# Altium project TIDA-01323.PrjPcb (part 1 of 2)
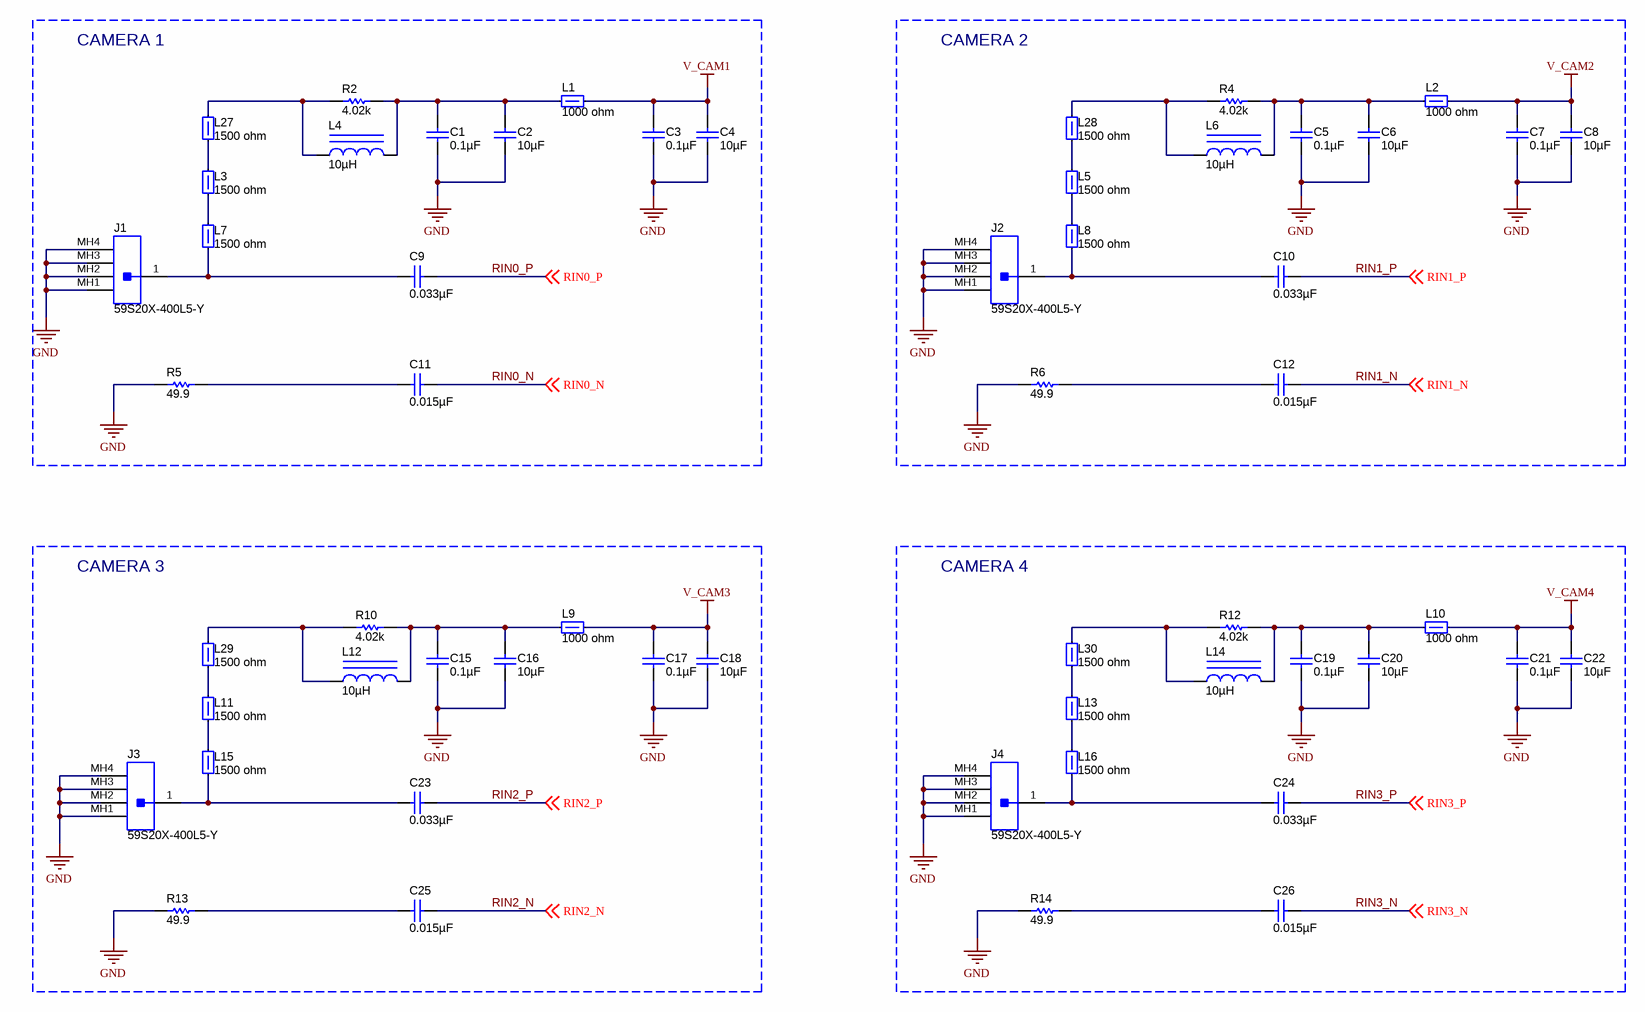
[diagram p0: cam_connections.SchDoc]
CopyrightYear: 2017; EVM_Orderable: NO; PCB_Layout: Krypton Solutions; PCB_Rev: E1.0; PRJ_Customer: Public Release; PRJ_Engineer: Jeramie Bianchi; PRJ_Number: TIDA-01323; PRJ_Title: Four Channel Camera Board for TDA2Plus; SCH_Rev: E1.0; TechSupport: http://www.ti.com/support; TID: 01323
8 sheets, 311 parts. Net scope: global (net labels, ports and power ports of the same name join across sheets).
Board file: TIDA-01323.PcbDoc
Sheets:
  cam_connections.SchDoc
  V_Batt_Supply.SchDoc
  Bucks.SchDoc
  Deserializer.SchDoc
  Connectors.SchDoc
  Camera_Power.SchDoc
  uC.SchDoc
  Hardware.SchDoc

## Sheet cam_connections.SchDoc: cam_connections
size 431 x 279 mm; Date: Not shown in title block; ApprovedBy: Not shown in title block; CheckedBy: Not shown in title block; Author: Not shown in title block; CompanyName: Not shown in title block; DrawnBy: Jeramie Bianchi; Engineer: Not shown in title block; Organization: Not shown in title block; Address1: Not shown in title block; Address2: Not shown in title block; Address3: Not shown in title block; Address4: Not shown in title block; DocumentNumber: 1; Revision: Use project parameter SCH_Rev; SheetNumber: 1; SheetTotal: 8; PageSetup: Record=PageOptions¦CenterHorizontal=True¦CenterVertical=True¦PrintScale=0.64¦XCorrection=1.00¦YCorrection=1.00¦PrintKind=0¦BorderSize=5000000¦LeftOffset=0¦BottomOffset=0¦Orientation=2¦PaperLength=1000¦PaperWidth=1000¦Scale=100¦PaperSource=15¦PrintQuality=-3¦MediaType=1¦DitherType=10¦PrintScaleMode=1¦PaperKind=11x17¦PaperIndex=17

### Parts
C1  ValueDisplayed: 0.1µF  [0402]  (hidden comment: C1005X7R1H104K050BB)
C2  ValueDisplayed: 10µF  [0603L]  (hidden comment: C1608X5R1E106M080AC)
C3  ValueDisplayed: 0.1µF  [0402]  (hidden comment: C1005X7R1H104K050BB)
C4  ValueDisplayed: 10µF  [0603L]  (hidden comment: C1608X5R1E106M080AC)
C5  ValueDisplayed: 0.1µF  [0402]  (hidden comment: C1005X7R1H104K050BB)
C6  ValueDisplayed: 10µF  [0603L]  (hidden comment: C1608X5R1E106M080AC)
C7  ValueDisplayed: 0.1µF  [0402]  (hidden comment: C1005X7R1H104K050BB)
C8  ValueDisplayed: 10µF  [0603L]  (hidden comment: C1608X5R1E106M080AC)
C9  ValueDisplayed: 0.033µF  [0402]  (hidden comment: CGA2B3X7R1H333K050BB)
C10  ValueDisplayed: 0.033µF  [0402]  (hidden comment: CGA2B3X7R1H333K050BB)
C11  ValueDisplayed: 0.015µF  [0402]  (hidden comment: CGA2B3X7R1H153K050BB)
C12  ValueDisplayed: 0.015µF  [0402]  (hidden comment: CGA2B3X7R1H153K050BB)
C15  ValueDisplayed: 0.1µF  [0402]  (hidden comment: C1005X7R1H104K050BB)
C16  ValueDisplayed: 10µF  [0603L]  (hidden comment: C1608X5R1E106M080AC)
C17  ValueDisplayed: 0.1µF  [0402]  (hidden comment: C1005X7R1H104K050BB)
C18  ValueDisplayed: 10µF  [0603L]  (hidden comment: C1608X5R1E106M080AC)
C19  ValueDisplayed: 0.1µF  [0402]  (hidden comment: C1005X7R1H104K050BB)
C20  ValueDisplayed: 10µF  [0603L]  (hidden comment: C1608X5R1E106M080AC)
C21  ValueDisplayed: 0.1µF  [0402]  (hidden comment: C1005X7R1H104K050BB)
C22  ValueDisplayed: 10µF  [0603L]  (hidden comment: C1608X5R1E106M080AC)
C23  ValueDisplayed: 0.033µF  [0402]  (hidden comment: CGA2B3X7R1H333K050BB)
C24  ValueDisplayed: 0.033µF  [0402]  (hidden comment: CGA2B3X7R1H333K050BB)
C25  ValueDisplayed: 0.015µF  [0402]  (hidden comment: CGA2B3X7R1H153K050BB)
C26  ValueDisplayed: 0.015µF  [0402]  (hidden comment: CGA2B3X7R1H153K050BB)
J1  59S20X-400L5-Y  [Rosenberger_59S20X-400L5]
J2  59S20X-400L5-Y  [Rosenberger_59S20X-400L5]
J3  59S20X-400L5-Y  [Rosenberger_59S20X-400L5]
J4  59S20X-400L5-Y  [Rosenberger_59S20X-400L5]
L1  value 1000 ohm  [0603L]  (hidden comment: BLM18AG102SN1D)
L2  value 1000 ohm  [0603L]  (hidden comment: BLM18AG102SN1D)
L3  value 1500 ohm  [0603]  (hidden comment: BLM18HE152SN1D)
L4  ValueDisplayed: 10µH  [LQH3NP_G0]  (hidden comment: LQH3NPN100NG0)
L5  value 1500 ohm  [0603]  (hidden comment: BLM18HE152SN1D)
L6  ValueDisplayed: 10µH  [LQH3NP_G0]  (hidden comment: LQH3NPN100NG0)
L7  value 1500 ohm  [0603]  (hidden comment: BLM18HE152SN1D)
L8  value 1500 ohm  [0603]  (hidden comment: BLM18HE152SN1D)
L9  value 1000 ohm  [0603L]  (hidden comment: BLM18AG102SN1D)
L10  value 1000 ohm  [0603L]  (hidden comment: BLM18AG102SN1D)
L11  value 1500 ohm  [0603]  (hidden comment: BLM18HE152SN1D)
L12  ValueDisplayed: 10µH  [LQH3NP_G0]  (hidden comment: LQH3NPN100NG0)
L13  value 1500 ohm  [0603]  (hidden comment: BLM18HE152SN1D)
L14  ValueDisplayed: 10µH  [LQH3NP_G0]  (hidden comment: LQH3NPN100NG0)
L15  value 1500 ohm  [0603]  (hidden comment: BLM18HE152SN1D)
L16  value 1500 ohm  [0603]  (hidden comment: BLM18HE152SN1D)
L27  value 1500 ohm  [0603]  (hidden comment: BLM18HE152SN1D)
L28  value 1500 ohm  [0603]  (hidden comment: BLM18HE152SN1D)
L29  value 1500 ohm  [0603]  (hidden comment: BLM18HE152SN1D)
L30  value 1500 ohm  [0603]  (hidden comment: BLM18HE152SN1D)
R2  ValueDisplayed: 4.02k  [0603]  (hidden comment: CRCW06034K02FKEA)
R4  ValueDisplayed: 4.02k  [0603]  (hidden comment: CRCW06034K02FKEA)
R5  ValueDisplayed: 49.9  [0402]  (hidden comment: CRCW040249R9FKED)
R6  ValueDisplayed: 49.9  [0402]  (hidden comment: CRCW040249R9FKED)
R10  ValueDisplayed: 4.02k  [0603]  (hidden comment: CRCW06034K02FKEA)
R12  ValueDisplayed: 4.02k  [0603]  (hidden comment: CRCW06034K02FKEA)
R13  ValueDisplayed: 49.9  [0402]  (hidden comment: CRCW040249R9FKED)
R14  ValueDisplayed: 49.9  [0402]  (hidden comment: CRCW040249R9FKED)

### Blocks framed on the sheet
CAMERA 1: C1-C4 C9 C11 J1 L1 L3 L4 L7 L27 R2 R5
CAMERA 2: C5-C8 C10 C12 J2 L2 L5 L6 L8 L28 R4 R6
CAMERA 3: C15-C18 C23 C25 J3 L9 L11 L12 L15 L29 R10 R13
CAMERA 4: C19-C22 C24 C26 J4 L10 L13 L14 L16 L30 R12 R14

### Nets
GND: C1.2 C2.2 C3.2 C4.2 C5.2 C6.2 C7.2 C8.2 C15.2 C16.2 C17.2 C18.2 C19.2 C20.2 C21.2 C22.2 J1.MH1 J1.MH2 J1.MH3 J1.MH4 J2.MH1 J2.MH2 J2.MH3 J2.MH4 J3.MH1 J3.MH2 J3.MH3 J3.MH4 J4.MH1 J4.MH2 J4.MH3 J4.MH4 R5.1 R6.1 R13.1 R14.1
V_CAM1: C3.1 C4.1 L1.1
V_CAM2: C7.1 C8.1 L2.1
V_CAM3: C17.1 C18.1 L9.1
V_CAM4: C21.1 C22.1 L10.1
RIN0_N: C11.2 ; off-sheet RIN0_N
RIN0_P: C9.2 ; off-sheet RIN0_P
RIN1_N: C12.2 ; off-sheet RIN1_N
RIN1_P: C10.2 ; off-sheet RIN1_P
RIN2_N: C25.2 ; off-sheet RIN2_N
RIN2_P: C23.2 ; off-sheet RIN2_P
RIN3_N: C26.2 ; off-sheet RIN3_N
RIN3_P: C24.2 ; off-sheet RIN3_P
NetC1_1: C1.1 C2.1 L1.2 L4.2 R2.2
NetC5_1: C5.1 C6.1 L2.2 L6.2 R4.2
NetC9_1: C9.1 J1.1 L7.1
NetC10_1: C10.1 J2.1 L8.1
NetC11_1: C11.1 R5.2
NetC12_1: C12.1 R6.2
NetC15_1: C15.1 C16.1 L9.2 L12.2 R10.2
NetC19_1: C19.1 C20.1 L10.2 L14.2 R12.2
NetC23_1: C23.1 J3.1 L15.1
NetC24_1: C24.1 J4.1 L16.1
NetC25_1: C25.1 R13.2
NetC26_1: C26.1 R14.2
NetL3_1: L3.1 L7.2
NetL3_2: L3.2 L27.1
NetL4_1: L4.1 L27.2 R2.1
NetL5_1: L5.1 L8.2
NetL5_2: L5.2 L28.1
NetL6_1: L6.1 L28.2 R4.1
NetL11_1: L11.1 L15.2
NetL11_2: L11.2 L29.1
NetL12_1: L12.1 L29.2 R10.1
NetL13_1: L13.1 L16.2
NetL13_2: L13.2 L30.1
NetL14_1: L14.1 L30.2 R12.1

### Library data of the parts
C1 C3 C5 C7 C15 C17 C19 C21 = C1005X7R1H104K050BB: CAP, CERM, 0.1 µF, 50 V, +/- 10%, X7R, 0402; Manufacturer: TDK; Polarized: N; CompType: Capacitor; Value: 0.1uF; U/M: EA; Cap_F: 0.0000001; Tolerance_%: 10; Value1: Unknown; VDC_V: 50; Value2: 50V; TaMin_C: -55; TaMax_C: 125
C2 C4 C6 C8 C16 C18 C20 C22 = C1608X5R1E106M080AC: CAP, CERM, 10 µF, 25 V, +/- 20%, X5R, 0603; Manufacturer: TDK; Polarized: N; CompType: Capacitor; Value: 10uF; U/M: EA; Cap_F: 0.00001; Tolerance_%: 20; ESR_ohm: 0.004639; Value1: 0.004639 ohm; VDC_V: 25; Value2: 25V; IRMS_A: 2.41407; TaMin_C: -55; TaMax_C: 85; Cap_Case: 0603; SizeArea_mm2: 1.28; SizeAreaWB_mm2: 4.68; SizeX_mm: 1.6; SizeY_mm: 0.8; SizeZ_mm: 1; AEC Category: Q200
C9 C10 C23 C24 = CGA2B3X7R1H333K050BB: CAP, CERM, 0.033 µF, 50 V, +/- 10%, X7R, AEC-Q200 Grade 1, 0402; Manufacturer: TDK; Polarized: N; CompType: Capacitor; Value: 0.033uF; U/M: EA; Cap_F: 0.000000033; Tolerance_%: 10; ESR_ohm: 0.098477; Value1: 0.098477 ohm; VDC_V: 50; Value2: 50V; IRMS_A: 0.53078; TaMin_C: -55; TaMax_C: 125; SizeArea_mm2: 0.5; SizeAreaWB_mm2: 3; SizeX_mm: 1; SizeZ_mm: 0.6; AEC Category: Q200; AEC Qualified: Y
C11 C12 C25 C26 = CGA2B3X7R1H153K050BB: CAP, CERM, 0.015 µF, 50 V,+/- 10%, X7R, AEC-Q200 Grade 1, 0402; Manufacturer: TDK; Polarized: N; CompType: Capacitor; Value: 0.015uF; U/M: EA; Cap_F: 0.000000015; Tolerance_%: 10; ESR_ohm: 0.2162; Value1: 0.2162 ohm; VDC_V: 50; Value2: 50V; IRMS_A: 0.379389; TaMin_C: -55; TaMax_C: 125; SizeArea_mm2: 0.5; SizeAreaWB_mm2: 3; SizeX_mm: 1; SizeZ_mm: 0.6; AEC Category: Q200; AEC Qualified: Y
J1-J4 = 59S20X-400L5-Y: RIGHT ANGLE PLUG FOR PCB; Manufacturer: Rosenberger; SymbolCreator: x0208325
L1 L2 L9 L10 = BLM18AG102SN1D: Ferrite Bead, 1000 ohm @ 100 MHz, 0.4 A, 0603; Manufacturer: MuRata; Imax_A: 0.4; DCR_ohm: 0.5; Value1: 0.5 ohm; Value2: 0.4A; ZTyp@100MHz_Ohm: 1000
L3 L5 L11 L13 L28-L30 = BLM18HE152SN1D: Ferrite Bead, 1500 ohm @ 100 MHz, 0.5 A, 0603; Manufacturer: MuRata; Imax_A: 0.5; Value1: 0.5 ohm; Value2: 0.5A; SizeAreaWB_mm2: 4.68; SizeArea_mm2: 1.28; SizeX_mm: 1.6; SizeY_mm: 0.8; SizeZ_mm: 1; ZTyp@100MHz_Ohm: 1500
L4 L6 L12 L14 = LQH3NPN100NG0: Inductor, Wirewound, Ferrite, 10 µH, 0.5 A, 0.57 ohm, SMD; Manufacturer: MuRata; Value: 10uH; Ind_H: 10.0E-6; Imax_A: 0.5; Irms: 0.63A @ 40C rise; Isat: 0.5A @ 30% inductance drop; DCR_ohm: 0.57; Value2: 0.5A; SizeAreaWB_mm2: 16; SizeArea_mm2: 9; SizeX_mm: 3; SizeZ_mm: 1; AEC Category: Q200
L7 L8 L15 L16 = BLM18HE152SN1D: Ferrite Bead, 1500 ohm @ 100 MHz, 0.5 A, 0603; Manufacturer: MuRata; Imax_A: 0.5; Value1: 0.5 ohm; Value2: 0.5A; ZTyp@100MHz_Ohm: 1500
L27 = BLM18HE152SN1D: Ferrite Bead, 1500 ohm @ 100 MHz, 0.5 A, 0603; Manufacturer: MuRata; Value1: 0.5 ohm; Value2: 0.5A; Imax_A: 0.5; SizeAreaWB_mm2: 4.68; SizeArea_mm2: 1.28; SizeX_mm: 1.6; SizeY_mm: 0.8; SizeZ_mm: 1; ZTyp@100MHz_Ohm: 1500
R2 R4 R10 R12 = CRCW06034K02FKEA: RES, 4.02 k, 1%, 0.1 W, 0603; Manufacturer: Vishay-Dale; CompType: Resistor; Value: 4.02k; Res_ohm: 4020; Value_Code: 4k02; Tolerance_%: 1; Power_W: 0.1; Value2: 0.1W; VDC_V: 75; TempCo: 100 ppm/C; EIA_Code: E96; U/M: EA; SizeArea_mm2: 1.28; SizeX_mm: 1.6; SizeY_mm: 0.8; AEC Category: Q200
R5 R6 R13 R14 = CRCW040249R9FKED: RES, 49.9, 1%, 0.063 W, 0402; Manufacturer: Vishay-Dale; CompType: Resistor; Value: 49.9; Value_Code: 49R9; Tolerance_%: 1; Power_W: 0.063; Value2: 0.063W; VDC_V: 50; TempCo: 100 ppm/C; EIA_Code: E96; U/M: EA; SizeArea_mm2: 0.5; SizeZ_mm: 0.6; AEC Category: Q200

## Sheet V_Batt_Supply.SchDoc: V_Batt_Supply
size 431 x 279 mm; Date: Not shown in title block; ApprovedBy: Not shown in title block; CheckedBy: Not shown in title block; Author: Not shown in title block; CompanyName: Not shown in title block; DrawnBy: Jeramie Bianchi; Engineer: Not shown in title block; Organization: Not shown in title block; Address1: Not shown in title block; Address2: Not shown in title block; Address3: Not shown in title block; Address4: Not shown in title block; DocumentNumber: 2; Revision: Use project parameter SCH_Rev; SheetNumber: 2; SheetTotal: 8; PageSetup: Record=PageOptions¦CenterHorizontal=True¦CenterVertical=True¦PrintScale=0.62¦XCorrection=1.00¦YCorrection=1.00¦PrintKind=0¦BorderSize=5000000¦LeftOffset=0¦BottomOffset=0¦Orientation=2¦PaperLength=1000¦PaperWidth=1000¦Scale=100¦PaperSource=15¦PrintQuality=600¦MediaType=1¦DitherType=10¦PrintScaleMode=1¦PaperKind=Letter
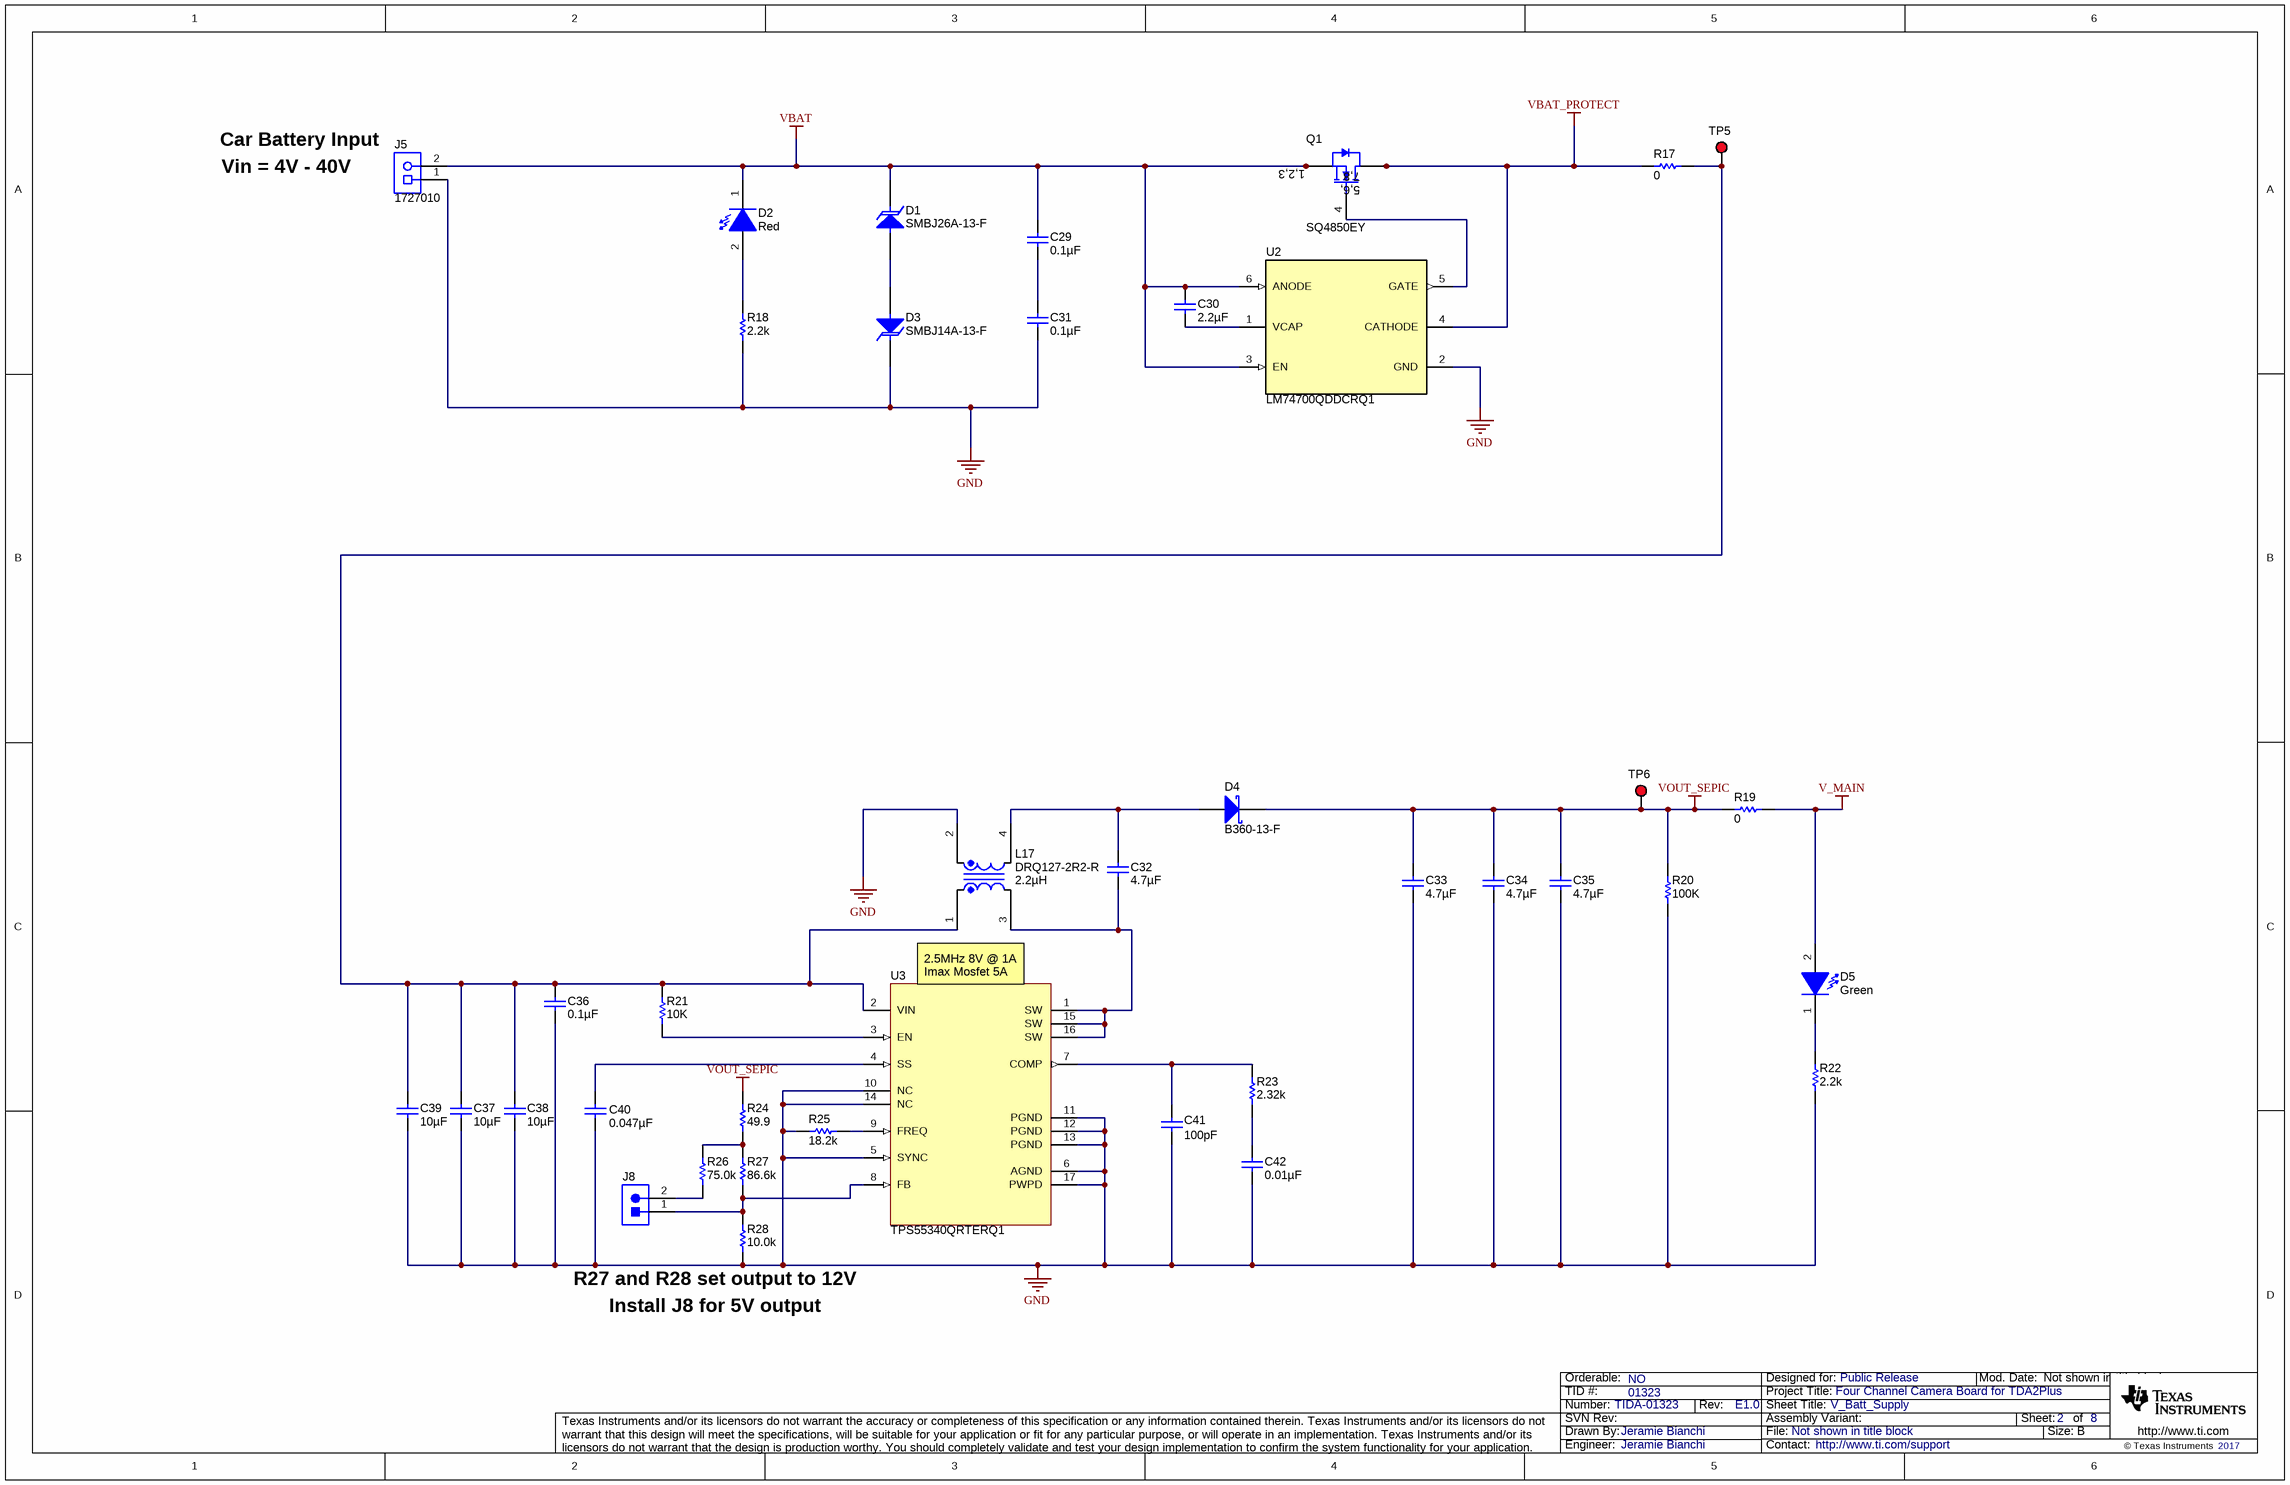
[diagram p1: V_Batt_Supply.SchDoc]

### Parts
C29  ValueDisplayed: 0.1µF  [0402]  (hidden comment: CGA2B3X7R1H104M050BB)
C30  ValueDisplayed: 2.2µF  [0603]  (hidden comment: GRM188R71A225KE15D)
C31  ValueDisplayed: 0.1µF  [0402]  (hidden comment: CGA2B3X7R1H104M050BB)
C32  ValueDisplayed: 4.7µF  [1206_190]  (hidden comment: C3216X7R1E475M160AC)
C33  ValueDisplayed: 4.7µF  [1206_190]  (hidden comment: C3216X7R1E475M160AC)
C34  ValueDisplayed: 4.7µF  [1206_190]  (hidden comment: C3216X7R1E475M160AC)
C35  ValueDisplayed: 4.7µF  [1206_190]  (hidden comment: C3216X7R1E475M160AC)
C36  ValueDisplayed: 0.1µF  [0402]  (hidden comment: GRM155R70J104KA01D)
C37  ValueDisplayed: 10µF  [1206_180]  (hidden comment: GRM31CR71E106KA12L)
C38  ValueDisplayed: 10µF  [1206_180]  (hidden comment: GRM31CR71E106KA12L)
C39  ValueDisplayed: 10µF  [1206_180]  (hidden comment: GRM31CR71E106KA12L)
C40  ValueDisplayed: 0.047µF  [0402]  (hidden comment: GRM155R70J473KA01D)
C41  ValueDisplayed: 100pF  [0402]  (hidden comment: CC0402KRX7R9BB101)
C42  ValueDisplayed: 0.01µF  [0402]  (hidden comment: GRM155R71C103KA01D)
D1  SMBJ26A-13-F  [SMB]
D2  value Red  [SML-P1_RED]  (hidden comment: SML-P12UTT86)
D3  SMBJ14A-13-F  [SMB]
D4  B360-13-F  [SMC]
D5  value Green  [SML-P1_GREEN]  (hidden comment: SML-P12PTT86)
J5  1727010  [PhoenixConact_1727010]
J8  PEC02SAAN  [CONN_PEC02SAAN]  (value not drawn)
L17  DRQ127-2R2-R  ValueDisplayed: 2.2µH  [DRQ127]
Q1  SQ4850EY  [SOIC-8]
R17  ValueDisplayed: 0  [2010]  (hidden comment: CRCW20100000Z0EF)
R18  ValueDisplayed: 2.2k  [0402]  (hidden comment: CRCW04022K20JNED)
R19  value 0  [0805_HV]  (hidden comment: CRCW08050000Z0EA)
R20  value 100K  [1206]  (hidden comment: CRCW1206100KJNEA)
R21  value 10K  [0402]  (hidden comment: CRCW040210K0JNED)
R22  ValueDisplayed: 2.2k  [0402]  (hidden comment: CRCW04022K20JNED)
R23  value 2.32k  [0402]  (hidden comment: CRCW04022K32FKED)
R24  value 49.9  [0402]  (hidden comment: CRCW040249R9FKED)
R25  value 18.2k  [0402]  (hidden comment: CRCW040218K2FKED)
R26  ValueDisplayed: 75.0k  [0402]  (hidden comment: CRCW040275K0FKED)
R27  ValueDisplayed: 86.6k  [0402]  (hidden comment: CRCW040286K6FKED)
R28  ValueDisplayed: 10.0k  [0402]  (hidden comment: CRCW040210K0FKED)
TP5  5000  [Keystone5000]  (value not drawn)
TP6  5000  [Keystone5000]  (value not drawn)
U2  LM74700QDDCRQ1  [DDC0006A_N]
U3  TPS55340QRTERQ1  [RTE0016C]

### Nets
GND: C31.2 C33.2 C34.2 C35.2 C36.2 C37.2 C38.2 C39.2 C40.2 C41.2 C42.2 D3.1(K) J5.1 L17.2 R18.1 R20.1 R22.1 R25.1 R28.1 U2.2(GND) U3.5(SYNC) U3.6(AGND) U3.10(NC) U3.11(PGND) U3.12(PGND) U3.13(PGND) U3.14(NC) U3.17(PWPD)
V_MAIN: D5.2(A) R19.2
VBAT: C29.1 C30.1 D1.1(K) D2.1(K) J5.2 Q1.1(S) Q1.2(S) Q1.3(S) U2.3(EN) U2.6(ANODE)
VBAT_PROTECT: Q1.5(D) Q1.6(D) Q1.7(D) Q1.8(D) R17.1 U2.4(CATHODE)
VOUT_SEPIC: C33.1 C34.1 C35.1 D4.1(K) R19.1 R20.2 R24.1 TP6.1
NetC29_2: C29.2 C31.1
NetC30_2: C30.2 U2.1(VCAP)
NetC32_1: C32.1 D4.2(A) L17.4
NetC32_2: C32.2 L17.3 U3.1(SW) U3.15(SW) U3.16(SW)
NetC36_1: C36.1 C37.1 C38.1 C39.1 L17.1 R17.2 R21.1 TP5.1 U3.2(VIN)
NetC40_1: C40.1 U3.4(SS)
NetC41_1: C41.1 R23.2 U3.7(COMP)
NetC42_1: C42.1 R23.1
NetD1_2: D1.2(A) D3.2(A)
NetD2_2: D2.2(A) R18.2
NetD5_1: D5.1(K) R22.2
NetJ8_1: J8.1 R27.1 R28.2 U3.8(FB)
NetJ8_2: J8.2 R26.1
NetQ1_4: Q1.4(G) U2.5(GATE)
NetR21_2: R21.2 U3.3(EN)
NetR24_2: R24.2 R26.2 R27.2
NetR25_2: R25.2 U3.9(FREQ)

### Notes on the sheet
- Vin = 4V - 40V
- (near J5) Car Battery Input
- 2.5MHz 8V @ 1A
  Imax Mosfet 5A
- (near R28) R27 and R28 set output to 12V
- (near R28) Install J8 for 5V output

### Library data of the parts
C29 C31 = CGA2B3X7R1H104M050BB: CAP, CERM, 0.1 µF, 50 V, +/- 20%, X7R, AEC-Q200 Grade 1, 0402; Manufacturer: TDK; Polarized: N; CompType: Capacitor; Value: 0.1uF; U/M: EA; Cap_F: 0.0000001; Tolerance_%: 20; Value1: Unknown; VDC_V: 50; Value2: 50V; TaMin_C: -55; TaMax_C: 125; AEC Category: Q200; AEC Qualified: Y; AEC Grade: 1
C30 = GRM188R71A225KE15D: CAP, CERM, 2.2 µF, 10 V, +/- 10%, X7R, 0603; Manufacturer: MuRata; Polarized: N; CompType: Capacitor; Value: 2.2uF; U/M: EA; Cap_F: 0.0000022; Tolerance_%: 10; ESR_ohm: 0.009; Value1: 0.009 ohm; Value2: 10V; TaMin_C: -55; TaMax_C: 125
C32-C35 = C3216X7R1E475M160AC: CAP, CERM, 4.7 µF, 25 V, +/- 20%, X7R, 1206_190; Manufacturer: TDK; Polarized: N; CompType: Capacitor; Value: 4.7uF; U/M: EA; Cap_F: 0.0000047; Tolerance_%: 20; Value1: Unknown; VDC_V: 25; Value2: 25V; TaMin_C: -55; TaMax_C: 125; Cap_Case: 1206; SizeArea_mm2: 5.12; SizeAreaWB_mm2: 10.92; SizeX_mm: 3.2; SizeY_mm: 1.6; SizeZ_mm: 1.9; AEC Category: Q200
C36 = GRM155R70J104KA01D: Cap, Cer-X7R, 0.1uF, 6.3V, 10%, 0402; Manufacturer: MuRata; Polarized: N; CompType: Capacitor; U/M: EA; Cap_F: 0.0000001; Tolerance_%: 10; Value1: Unknown; VDC_V: 6.3; TempCo: X7R; TaMin_C: -55; TaMax_C: 125; EN: 102-1-01892; Mfg: MURATA MANUFACTURING CO,LTD; Onhand: 0
C37-C39 = GRM31CR71E106KA12L: CAP, CERM, 10 µF, 25 V, +/- 10%, X7R, 1206; Manufacturer: MuRata; Polarized: N; CompType: Capacitor; Value: 10uF; U/M: EA; Cap_F: 0.00001; Tolerance_%: 10; Value1: Unknown; VDC_V: 25; Value2: 25V; TaMin_C: -55; TaMax_C: 125; Cap_Case: 2220; SizeArea_mm2: 5.12; SizeAreaWB_mm2: 10.92; SizeX_mm: 3.2; SizeY_mm: 1.6; SizeZ_mm: 1.8; AEC Category: Q200
C40 = GRM155R70J473KA01D: Cap, Cer-X7R, 0.047uF, 6.3V, 10%, 0402; Manufacturer: MuRata; Polarized: N; CompType: Capacitor; U/M: EA; Cap_F: 0.000000047; Tolerance_%: 10; Value1: Unknown; VDC_V: 6.3; TempCo: X7R; TaMin_C: -55; TaMax_C: 125; EN: 102-1-01894; Mfg: MURATA MANUFACTURING CO,LTD; Onhand: 0
C41 = CC0402KRX7R9BB101: Cap, Cer-X7R, 100pF, 50V, 10%, 0402; Manufacturer: Yageo America; PART Name: SCH_LIB\CAP_NP; Polarized: N; CompType: Capacitor; U/M: EA; Cap_F: 0.0000000001; Tolerance_%: 10; Value1: Unknown; VDC_V: 50; TempCo: X7R; TaMin_C: -55; TaMax_C: 125; DECAL Name: 0402,0402_HD; EN: 102-1-00053; Mfg: YAGEO; Onhand: 16933
C42 = GRM155R71C103KA01D: Cap, Cer-X7R, 10000pF, 16V, 10%, 0402; Manufacturer: MuRata; Polarized: N; CompType: Capacitor; U/M: EA; Cap_F: 0.00000001; Tolerance_%: 10; Value1: Unknown; VDC_V: 16; TempCo: X7R; TaMin_C: -55; TaMax_C: 125; EN: 102-1-01895; Mfg: MURATA MANUFACTURING CO,LTD; Onhand: 0
D1 = SMBJ26A-13-F: Diode, TVS, Uni, 26 V, 600 W, SMB; Manufacturer: Diodes Inc.; Value: 26V; U/M: EA; Power_W: 5; Vr_V: 26; Value1: 5W
D2 = SML-P12UTT86: LED, Red, SMD; Manufacturer: Rohm; Type: AlInGaP; Vf_V: 2; Value2: 2V; Io_A: 0.02; Value1: W; U/M: EA
D3 = SMBJ14A-13-F: Diode, TVS, Uni, 14 V, 600 W, SMB; Manufacturer: Diodes Inc.; Value: 14V; U/M: EA; Power_W: 5; Vr_V: 14; Value1: 5W
D4 = B360-13-F: Diode, Schottky, 3A, 60V, SMC; Manufacturer: Diodes Inc.; U/M: EA; Vf_V: 0.7; Value2: 0.7V; Io_A: 3; Vr_V: 60; TJmax_C: 125; RJC_CperW: 20; DECAL Name: DIO-SMC_CASE_403; EN: 106-2-00038; Mfg: DIODES INCORPORATED; Onhand: 10
D5 = SML-P12PTT86: LED, Green, SMD; Manufacturer: Rohm; Type: AlInGaP; Vf_V: 2.2; Value2: 2.2V; Io_A: 0.02; Value1: W; U/M: EA
J5 = 1727010: Conn Term Block, 2POS, 3.81mm, TH; Manufacturer: Phoenix Contact; SymbolCreator: a0412235; CompType: Terminal Block; U/M: EA; Value: 2x1
J8 = PEC02SAAN: Header, 100mil, 2x1, Tin, TH; Manufacturer: Sullins Connector Solutions; SymbolCreator: a0412235; U/M: EA
L17 = DRQ127-2R2-R: Ind, Dual, 2.2uH, 20%, 6.23A, 8.05mE, Shielded, SMD; Manufacturer: Coiltronics; SymbolCreator: a0412235; Ind_H: 2.2E-6; CompType: Coupled Inductor; DCR_ohm: 3.73; Isat: 25.5; Tolerance_%: 20; EN: 103-1-00256; Onhand: 0
Q1 = SQ4850EY: MOSFET, N-CH, 60 V, 12 A, SOIC-8; Manufacturer: Vishay-Siliconix; Alternate Manufacturer: None; U/M: EA; ChType: N; Value: 60V; VdsMax_V: 60; Value1: 0.031 ohm; Rdson45_ohm: 0.031; Value2: 20 nC; QgTyp_nC: 20; IdsMax_A: 12; SizeAreaWB_mm2: 55.131; SizeArea_mm2: 29.351; SizeX_mm: 5.99; SizeY_mm: 4.9; SizeZ_mm: 1.75; AEC Category: Q101
R17 = CRCW20100000Z0EF: RES, 0, 5%, 0.75 W, 2010; Manufacturer: Vishay-Dale; CompType: Resistor; Value: 0; Value_Code: 0000; Tolerance_%: 5; Power_W: 0.75; Value2: 0.75W; TempCo: ppm/C; EIA_Code: E24; U/M: EA
R18 R22 = CRCW04022K20JNED: RES, 2.2 k, 5%, 0.063 W, 0402; Manufacturer: Vishay-Dale; CompType: Resistor; Value: 2.2k; Res_ohm: 2200; Value_Code: 2k20; Tolerance_%: 5; Power_W: 0.063; Value2: 0.063W; VDC_V: 50; TempCo: 200 ppm/C; EIA_Code: E24; U/M: EA
R19 = CRCW08050000Z0EA: Res, Chip, 0E, 1/8W, JUMP, 0805; Manufacturer: Vishay-Dale; CompType: Resistor; Value_Code: 0000; Tolerance_%: 5; Value1: 5%; Power_W: 0.125; Value2: 0.125W; VDC_V: 150; TempCo: 200 ppm/C; EIA_Code: E24; U/M: EA; EN: 101-1-03582; Mfg: VISHAY
R20 = CRCW1206100KJNEA: Res, Chip, 100K, 1/4W, 5%, 1206; Manufacturer: Vishay-Dale; PART Name: SCH_LIB\RES; CompType: Resistor; Res_ohm: 100000; Tolerance_%: 5; Power_W: 0.25; Value2: 0.25W; VDC_V: 200; TempCo: 200 ppm/C; EIA_Code: E24; U/M: EA; EN: 101-1-03324; Mfg: VISHAY; Onhand: 0
R21 = CRCW040210K0JNED: Res, Chip, 10K, 1/16W, 5%, 0402; Manufacturer: Vishay-Dale; PART Name: SCH_LIB\RES; CompType: Resistor; Res_ohm: 10000; Value_Code: 10k0; Tolerance_%: 5; Power_W: 0.063; Value2: 0.063W; VDC_V: 50; TempCo: 200 ppm/C; EIA_Code: E24; U/M: EA; EN: 101-1-02793; Mfg: VISHAY; Onhand: 7938
R23 = CRCW04022K32FKED: RES, 2.32k ohm, 1%, 0.063W, 0402; Manufacturer: Vishay-Dale; CompType: Resistor; Res_ohm: 2320; Value_Code: 2k32; Tolerance_%: 1; Power_W: 0.063; VDC_V: 50; TempCo: 100 ppm/C; EIA_Code: E96; U/M: EA; EN: 101-1-00328
R24 = CRCW040249R9FKED: RES, 49.9 ohm, 1%, 0.063W, 0402; Manufacturer: Vishay-Dale; CompType: Resistor; Value_Code: 49R9; Tolerance_%: 1; Power_W: 0.063; VDC_V: 50; TempCo: 100 ppm/C; EIA_Code: E96; U/M: EA; EN: 101-1-00168
R25 = CRCW040218K2FKED: RES, 18.2k ohm, 1%, 0.063W, 0402; Manufacturer: Vishay-Dale; CompType: Resistor; Res_ohm: 18200; Value_Code: 18k2; Tolerance_%: 1; Power_W: 0.063; VDC_V: 50; TempCo: 100 ppm/C; EIA_Code: E96; U/M: EA; EN: 101-1-00414
R26 = CRCW040275K0FKED: RES, 75.0 k, 1%, 0.063 W, 0402; Manufacturer: Vishay-Dale; CompType: Resistor; Value: 75.0k; Res_ohm: 75000; Value_Code: 75k0; Tolerance_%: 1; Power_W: 0.063; Value2: 0.063W; VDC_V: 50; TempCo: 100 ppm/C; SizeArea_mm2: 0.5; SizeZ_mm: 0.6; EIA_Code: E96; U/M: EA; AEC Category: Q200; Green_Lifecycle: Active; Green_REACh: Passed
R27 = CRCW040286K6FKED: RES, 86.6 k, 1%, 0.063 W, 0402; Manufacturer: Vishay-Dale; CompType: Resistor; Value: 86.6k; Res_ohm: 86600; Value_Code: 86k6; Tolerance_%: 1; Power_W: 0.063; Value2: 0.063W; VDC_V: 50; TempCo: 100 ppm/C; SizeArea_mm2: 0.5; SizeZ_mm: 0.6; EIA_Code: E96; U/M: EA; AEC Category: Q200; Green_Lifecycle: Active; Green_REACh: Passed
R28 = CRCW040210K0FKED: RES, 10.0 k, 1%, 0.063 W, 0402; Manufacturer: Vishay-Dale; CompType: Resistor; Value: 10.0k; Res_ohm: 10000; Value_Code: 10k0; Tolerance_%: 1; Power_W: 0.063; Value2: 0.063W; VDC_V: 50; TempCo: 100 ppm/C; SizeArea_mm2: 0.5; SizeZ_mm: 0.6; EIA_Code: E96; U/M: EA; AEC Category: Q200; Green_Lifecycle: Active; Green_REACh: Passed
TP5 TP6 = 5000: Test Point, Miniature, Red, TH; Manufacturer: Keystone; CompType: Test Point Loop; U/M: EA
U2 = LM74700QDDCRQ1: Low Iq Always ON Smart Diode Controller, DDC0006A (SOT-23-T-6); Manufacturer: Texas Instruments; SymbolCreator: Altium; CompType: IC; U/M: EA; SizeArea_mm2: 4.8675; SizeAreaWB_mm2: 10.4675; SizeX_mm: 1.65; SizeY_mm: 2.95; SizeZ_mm: 0.87
U3 = TPS55340QRTERQ1: Integrated 5-A 40-V Wide Input Range Boost/SEPIC/Flyback DC-DC Regulator, RTE0016C; Alternate PartNumber: TPS55340QRTETQ1; Manufacturer: Texas Instruments; SymbolCreator: x0208326; CompType: IC; U/M: EA

## Sheet Bucks.SchDoc: Camera_Switch_and_Bucks
size 431 x 279 mm; Date: Not shown in title block; ApprovedBy: Not shown in title block; CheckedBy: Not shown in title block; Author: Not shown in title block; CompanyName: Not shown in title block; DrawnBy: Jeramie Bianchi; Engineer: Not shown in title block; Organization: Not shown in title block; Address1: Not shown in title block; Address2: Not shown in title block; Address3: Not shown in title block; Address4: Not shown in title block; DocumentNumber: 3; Revision: Use project parameter SCH_Rev; SheetNumber: 3; SheetTotal: 8; PageSetup: Record=PageOptions¦CenterHorizontal=True¦CenterVertical=True¦PrintScale=0.64¦XCorrection=1.00¦YCorrection=1.00¦PrintKind=0¦BorderSize=5000000¦LeftOffset=0¦BottomOffset=0¦Orientation=2¦PaperLength=1000¦PaperWidth=1000¦Scale=100¦PaperSource=15¦PrintQuality=600¦MediaType=1¦DitherType=10¦PrintScaleMode=1¦PaperKind=Letter
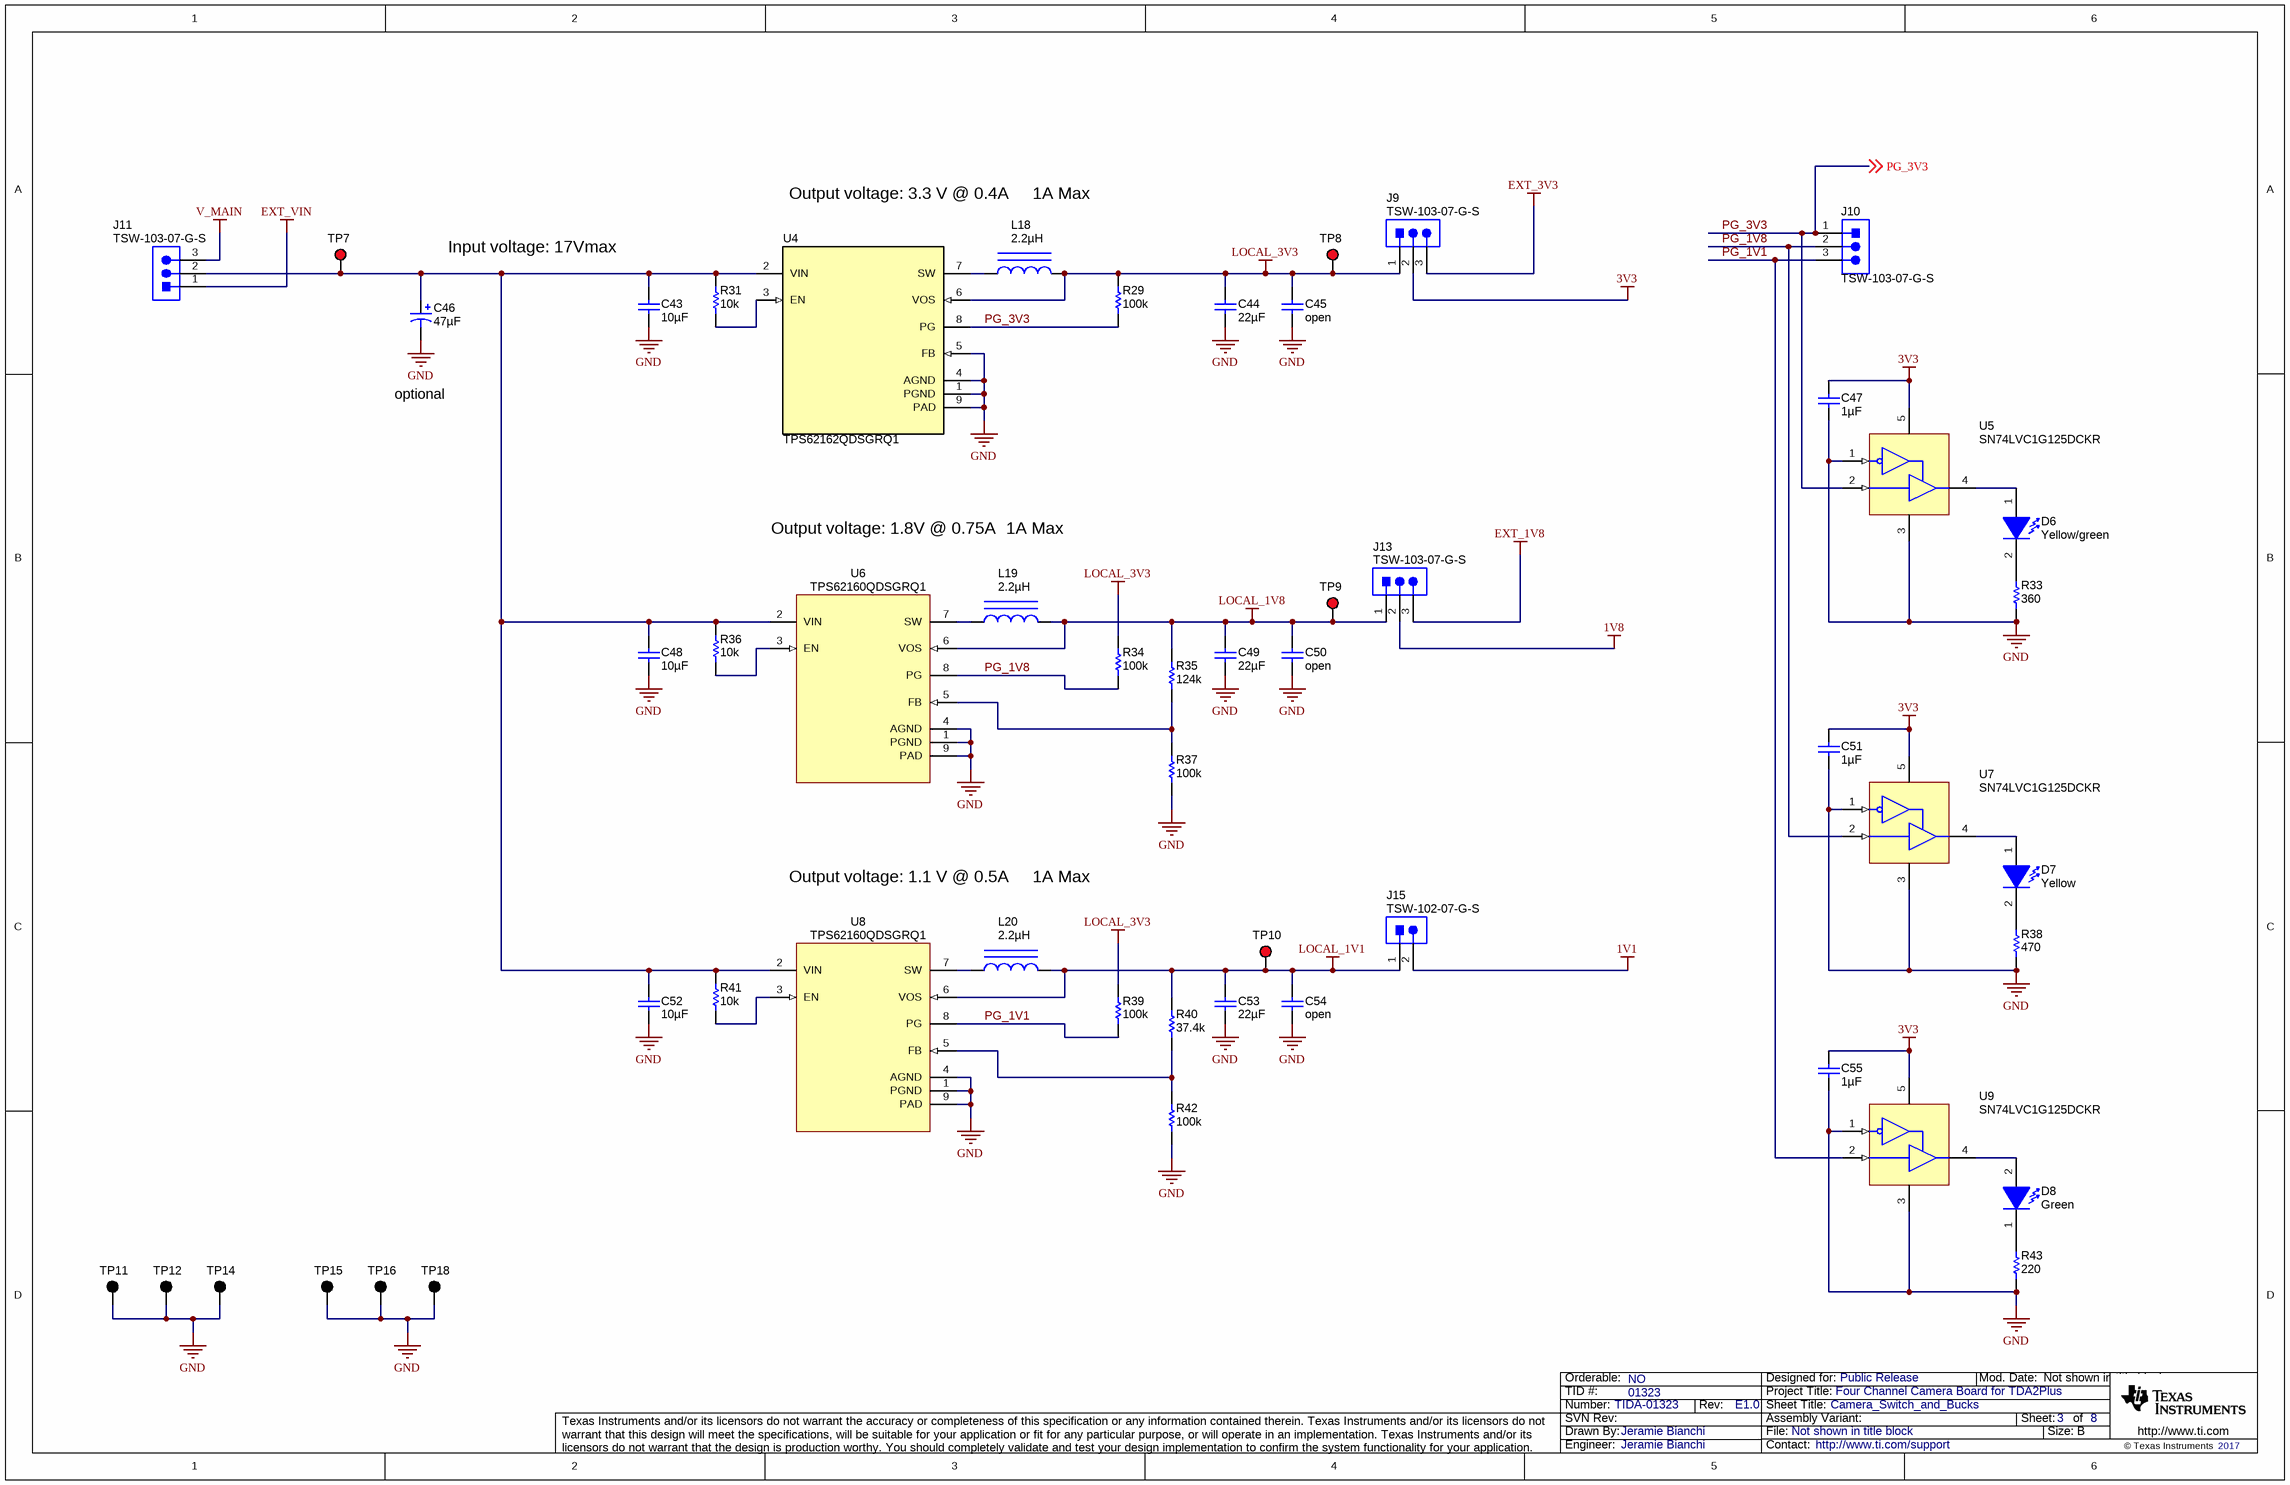
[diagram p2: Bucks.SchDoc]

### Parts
C43  ValueDisplayed: 10µF  [1206_180]  (hidden comment: GRM31CR71C106KAC7L)
C44  ValueDisplayed: 22µF  [1206_180]  (hidden comment: GRM31CR61C226KE15L)
C45  ValueDisplayed: open  [1206_180]  (hidden comment: GRM31CR61C226KE15L)
C46  ValueDisplayed: 47µF  [SM_RADIAL_D]  (hidden comment: EEE-FK1E470P)
C47  ValueDisplayed: 1µF  [0402]  (hidden comment: C1005JB1V105K050BC)
C48  ValueDisplayed: 10µF  [1206_180]  (hidden comment: GRM31CR71C106KAC7L)
C49  ValueDisplayed: 22µF  [1206_180]  (hidden comment: GRM31CR61C226KE15L)
C50  ValueDisplayed: open  [1206_180]  (hidden comment: GRM31CR61C226KE15L)
C51  ValueDisplayed: 1µF  [0402]  (hidden comment: C1005JB1V105K050BC)
C52  ValueDisplayed: 10µF  [1206_180]  (hidden comment: GRM31CR71C106KAC7L)
C53  ValueDisplayed: 22µF  [1206_180]  (hidden comment: GRM31CR61C226KE15L)
C54  ValueDisplayed: open  [1206_180]  (hidden comment: GRM31CR61C226KE15L)
C55  ValueDisplayed: 1µF  [0402]  (hidden comment: C1005JB1V105K050BC)
D6  value Yellow/green  [SML-P1_YELLOW-GREEN]  (hidden comment: SML-P12MTT86)
D7  value Yellow  [LED_SMLP12_Yellow]  (hidden comment: SML-P12YTT86)
D8  value Green  [SML-P1_GREEN]  (hidden comment: SML-P12PTT86)
J9  TSW-103-07-G-S  [TSW-103-07-G-S]
J10  TSW-103-07-G-S  [TSW-103-07-G-S]
J11  TSW-103-07-G-S  [TSW-103-07-G-S]
J13  TSW-103-07-G-S  [TSW-103-07-G-S]
J15  TSW-102-07-G-S  [TSW-102-07-G-S]
L18  ValueDisplayed: 2.2µH  [VLS201610ET]  (hidden comment: VLS201610HBX-2R2M)
L19  ValueDisplayed: 2.2µH  [VLS201610ET]  (hidden comment: VLS201610HBX-2R2M)
L20  ValueDisplayed: 2.2µH  [VLS201610ET]  (hidden comment: VLS201610HBX-2R2M)
R29  ValueDisplayed: 100k  [0603]  (hidden comment: CRCW0603100KFKEA)
R31  ValueDisplayed: 10k  [0402]  (hidden comment: CRCW040210K0JNED)
R33  ValueDisplayed: 360  [0402]  (hidden comment: CRCW0402360RJNED)
R34  ValueDisplayed: 100k  [0603]  (hidden comment: CRCW0603100KFKEA)
R35  ValueDisplayed: 124k  [0603]  (hidden comment: CRCW0603124KFKEA)
R36  ValueDisplayed: 10k  [0402]  (hidden comment: CRCW040210K0JNED)
R37  ValueDisplayed: 100k  [0603]  (hidden comment: CRCW0603100KFKEA)
R38  ValueDisplayed: 470  [0402]  (hidden comment: CRCW0402470RJNED)
R39  ValueDisplayed: 100k  [0603]  (hidden comment: CRCW0603100KFKEA)
R40  ValueDisplayed: 37.4k  [0603]  (hidden comment: CRCW060337K4FKEA)
R41  ValueDisplayed: 10k  [0402]  (hidden comment: CRCW040210K0JNED)
R42  ValueDisplayed: 100k  [0603]  (hidden comment: CRCW0603100KFKEA)
R43  ValueDisplayed: 220  [0402]  (hidden comment: CRCW0402220RJNED)
TP7  5000  [Keystone5000]  (value not drawn)
TP8  5000  [Keystone5000]  (value not drawn)
TP9  5000  [Keystone5000]  (value not drawn)
TP10  5000  [Keystone5000]  (value not drawn)
TP11  5001  [Keystone5001]  (value not drawn)
TP12  5001  [Keystone5001]  (value not drawn)
TP14  5001  [Keystone5001]  (value not drawn)
TP15  5001  [Keystone5001]  (value not drawn)
TP16  5001  [Keystone5001]  (value not drawn)
TP18  5001  [Keystone5001]  (value not drawn)
U4  TPS62162QDSGRQ1  [DSG0008A]
U5  SN74LVC1G125DCKR  [DCK0005A_N]
U6  TPS62160QDSGRQ1  [DSG0008A]
U7  SN74LVC1G125DCKR  [DCK0005A_N]
U8  TPS62160QDSGRQ1  [DSG0008A]
U9  SN74LVC1G125DCKR  [DCK0005A_N]

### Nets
1V1: J15.2
1V8: J13.2
3V3: C47.1 C51.1 C55.1 J9.2 U5.5(VCC) U7.5(VCC) U9.5(VCC)
EXT_1V8: J13.3
EXT_3V3: J9.3
EXT_VIN: J11.1
GND: C43.2 C44.2 C45.2 C46.2(-) C47.2 C48.2 C49.2 C50.2 C51.2 C52.2 C53.2 C54.2 C55.2 R33.2 R37.1 R38.1 R42.1 R43.1 TP11.1 TP12.1 TP14.1 TP15.1 TP16.1 TP18.1 U4.1(PGND) U4.4(AGND) U4.5(FB) U4.9(PAD) U5.1(~{OE}) U5.3(GND) U6.1(PGND) U6.4(AGND) U6.9(PAD) U7.1(~{OE}) U7.3(GND) U8.1(PGND) U8.4(AGND) U8.9(PAD) U9.1(~{OE}) U9.3(GND)
LOCAL_1V1: C53.1 C54.1 J15.1 L20.2 R40.2 TP10.1 U8.6(VOS)
LOCAL_1V8: C49.1 C50.1 J13.1 L19.2 R35.2 TP9.1 U6.6(VOS)
LOCAL_3V3: C44.1 C45.1 J9.1 L18.2 R29.2 R34.1 R39.1 TP8.1 U4.6(VOS)
V_MAIN: J11.3
PG_1V1: J10.3 R39.2 U8.8(PG) U9.2(A)
PG_1V8: J10.2 R34.2 U6.8(PG) U7.2(A)
PG_3V3: J10.1 R29.1 U4.8(PG) U5.2(A) ; off-sheet PG_3V3
NetC43_1: C43.1 C46.1(+) C48.1 C52.1 J11.2 R31.2 R36.2 R41.2 TP7.1 U4.2(VIN) U6.2(VIN) U8.2(VIN)
NetD6_1: D6.1(A) U5.4(Y)
NetD6_2: D6.2(K) R33.1
NetD7_1: D7.1(A) U7.4(Y)
NetD7_2: D7.2(K) R38.2
NetD8_1: D8.1(K) R43.2
NetD8_2: D8.2(A) U9.4(Y)
NetL18_1: L18.1 U4.7(SW)
NetL19_1: L19.1 U6.7(SW)
NetL20_1: L20.1 U8.7(SW)
NetR31_1: R31.1 U4.3(EN)
NetR35_1: R35.1 R37.2 U6.5(FB)
NetR36_1: R36.1 U6.3(EN)
NetR40_1: R40.1 R42.2 U8.5(FB)
NetR41_1: R41.1 U8.3(EN)

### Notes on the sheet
- Output voltage: 3.3 V @ 0.4A
- 1A Max
- Input voltage: 17Vmax
- optional
- Output voltage: 1.8V @ 0.75A
- Output voltage: 1.1 V @ 0.5A

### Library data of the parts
C43 C48 C52 = GRM31CR71C106KAC7L: CAP, CERM, 10 µF, 16 V, +/- 10%, X7R, 1206; Manufacturer: MuRata; Polarized: N; CompType: Capacitor; Value: 10uF; U/M: EA; Cap_F: 0.00001; Tolerance_%: 10; Value1: Unknown; VDC_V: 16; Value2: 16V; TaMin_C: -55; TaMax_C: 125; Cap_Case: 1206; SizeArea_mm2: 5.12; SizeAreaWB_mm2: 10.92; SizeX_mm: 3.2; SizeY_mm: 1.6; SizeZ_mm: 1.8; AEC Category: Q200
C44 C45 C49 C50 C53 C54 = GRM31CR61C226KE15L: CAP, CERM, 22 µF, 16 V, +/- 10%, X5R, 1206; Manufacturer: MuRata; Polarized: N; CompType: Capacitor; Value: 22uF; U/M: EA; Cap_F: 0.000022; Tolerance_%: 10; Value1: Unknown; VDC_V: 16; Value2: 16V; TaMin_C: -55; TaMax_C: 85; Cap_Case: 1206; SizeArea_mm2: 5.12; SizeAreaWB_mm2: 10.92; SizeX_mm: 3.2; SizeY_mm: 1.6; SizeZ_mm: 1.8; AEC Category: Q200
C46 = EEE-FK1E470P: CAP, AL, 47 µF, 25 V, +/- 20%, 0.36 ohm, SMD; Manufacturer: Panasonic; Polarized: Y; CompType: Capacitor; Value: 47uF; U/M: EA; Cap_F: 0.000047; Tolerance_%: 20; VDC_V: 25; Value2: 25V; ESR_ohm: 0.36; IRMS_A: 0.24; TaMin_C: -55; TaMax_C: 105; Cap_Case: D
C47 C51 C55 = C1005JB1V105K050BC: CAP, CERM, 1 µF, 35 V, +/- 10%, JB, 0402; Manufacturer: TDK; Polarized: N; CompType: Capacitor; Value: 1uF; U/M: EA; Cap_F: 0.000001; Tolerance_%: 10; Value1: Unknown; VDC_V: 35; Value2: 35V; TaMin_C: -25; TaMax_C: 85
D6 = SML-P12MTT86: LED, Yellow/green, SMD; Manufacturer: Rohm; Type: AlInGaP; Vf_V: 2.2; Value2: 2.2V; Io_A: 0.02; Value1: W; U/M: EA
D7 = SML-P12YTT86: LED, Yellow, SMD; Manufacturer: Rohm; Type: InGaN; Vf_V: 2.1; Value2: 2.1V; Io_A: 0.02; Tjmax_C: 85; Value1: W; U/M: EA
D8 = SML-P12PTT86: as D5 on sheet V_Batt_Supply
J9-J11 J13 = TSW-103-07-G-S: Header, 100mil, 3x1, Gold, TH; Manufacturer: Samtec; SymbolCreator: a0799628; U/M: EA
J15 = TSW-102-07-G-S: Header, 100mil, 2x1, Gold, TH; Manufacturer: Samtec; SymbolCreator: a0412235; U/M: EA
L18-L20 = VLS201610ET-2R2M: Inductor, Shielded, Ferrite, 2.2 µH, 1.45 A, 0.170 ohm, SMD; Manufacturer: TDK; Value: 2.2uH; Value2: 1.45A
R29 R34 R37 R39 R42 = CRCW0603100KFKEA: RES, 100 k, 1%, 0.1 W, 0603; Manufacturer: Vishay-Dale; CompType: Resistor; Value: 100k; Res_ohm: 100000; Tolerance_%: 1; Power_W: 0.1; Value2: 0.1W; VDC_V: 75; TempCo: 100 ppm/C; EIA_Code: E96; U/M: EA
R31 R36 R41 = CRCW040210K0JNED: RES, 10 k, 5%, 0.063 W, 0402; Manufacturer: Vishay-Dale; CompType: Resistor; Value: 10k; Res_ohm: 10000; Value_Code: 10k0; Tolerance_%: 5; Power_W: 0.063; Value2: 0.063W; VDC_V: 50; TempCo: 200 ppm/C; EIA_Code: E24; U/M: EA
R33 = CRCW0402360RJNED: RES, 360, 5%, 0.063 W, 0402; Manufacturer: Vishay-Dale; CompType: Resistor; Value: 360; Value_Code: 360R; Tolerance_%: 5; Power_W: 0.063; Value2: 0.063W; VDC_V: 50; TempCo: 200 ppm/C; EIA_Code: E24; U/M: EA
R35 = CRCW0603124KFKEA: RES, 124 k, 1%, 0.1 W, 0603; Manufacturer: Vishay-Dale; CompType: Resistor; Value: 124k; Res_ohm: 124000; Tolerance_%: 1; Power_W: 0.1; Value2: 0.1W; VDC_V: 75; TempCo: 100 ppm/C; EIA_Code: E96; U/M: EA
R38 = CRCW0402470RJNED: RES, 470, 5%, 0.063 W, 0402; Manufacturer: Vishay-Dale; CompType: Resistor; Value: 470; Value_Code: 470R; Tolerance_%: 5; Power_W: 0.063; Value2: 0.063W; VDC_V: 50; TempCo: 200 ppm/C; EIA_Code: E24; U/M: EA
R40 = CRCW060337K4FKEA: RES, 37.4 k, 1%, 0.1 W, 0603; Manufacturer: Vishay-Dale; CompType: Resistor; Value: 37.4k; Res_ohm: 37400; Value_Code: 37k4; Tolerance_%: 1; Power_W: 0.1; Value2: 0.1W; VDC_V: 75; TempCo: 100 ppm/C; EIA_Code: E96; U/M: EA
R43 = CRCW0402220RJNED: RES, 220, 5%, 0.063 W, 0402; Manufacturer: Vishay-Dale; CompType: Resistor; Value: 220; Value_Code: 220R; Tolerance_%: 5; Power_W: 0.063; Value2: 0.063W; VDC_V: 50; TempCo: 200 ppm/C; EIA_Code: E24; U/M: EA
TP7-TP10 = 5000: as TP5 on sheet V_Batt_Supply
TP11 TP12 TP14-TP16 TP18 = 5001: Test Point, Miniature, Black, TH; Manufacturer: Keystone; CompType: Test Point Loop; U/M: EA
U4 = TPS62162QDSGRQ1: 3V-17V 1A Automotive Step-Down Converters in 2x2SON, DSG0008A (WSON-8); Alternate PartNumber: TPS62162QDSGTQ1; Manufacturer: Texas Instruments; SymbolCreator: Altium; CompType: IC; U/M: EA; SizeArea_mm2: 4; SizeAreaWB_mm2: 9; SizeX_mm: 2; SizeZ_mm: 0.8
U5 U7 U9 = SN74LVC1G125DCKR: Single Bus Buffer Gate With 3-State Output, DCK0005A; Alternate PartNumber: SN74LVC1G125DCKT; Manufacturer: Texas Instruments; SymbolCreator: Altium; CompType: IC; U/M: EA
U6 U8 = TPS62160QDSGRQ1: 3-V to 17-V 1-A Step-Down Converter with DCS-Control™, DSG0008A; Alternate PartNumber: TPS62160QDSGTQ1; Manufacturer: Texas Instruments; SymbolCreator: Altium; CompType: IC; U/M: EA

## Sheet Deserializer.SchDoc: Deserializer
size 431 x 279 mm; Date: Not shown in title block; ApprovedBy: Not shown in title block; CheckedBy: Not shown in title block; Author: Not shown in title block; CompanyName: Not shown in title block; DrawnBy: Jeramie Bianchi; Engineer: Not shown in title block; Organization: Not shown in title block; Address1: Not shown in title block; Address2: Not shown in title block; Address3: Not shown in title block; Address4: Not shown in title block; DocumentNumber: 4; Revision: Use project parameter SCH_Rev; SheetNumber: 4; SheetTotal: 8; PageSetup: Record=PageOptions¦CenterHorizontal=True¦CenterVertical=True¦PrintScale=0.96¦XCorrection=1.00¦YCorrection=1.00¦PrintKind=0¦BorderSize=5000000¦LeftOffset=0¦BottomOffset=0¦Orientation=2¦PaperLength=1000¦PaperWidth=1000¦Scale=100¦PaperSource=15¦PrintQuality=600¦MediaType=1¦DitherType=10¦PrintScaleMode=1¦PaperKind=Tabloid (11 x 17")¦PaperIndex=17
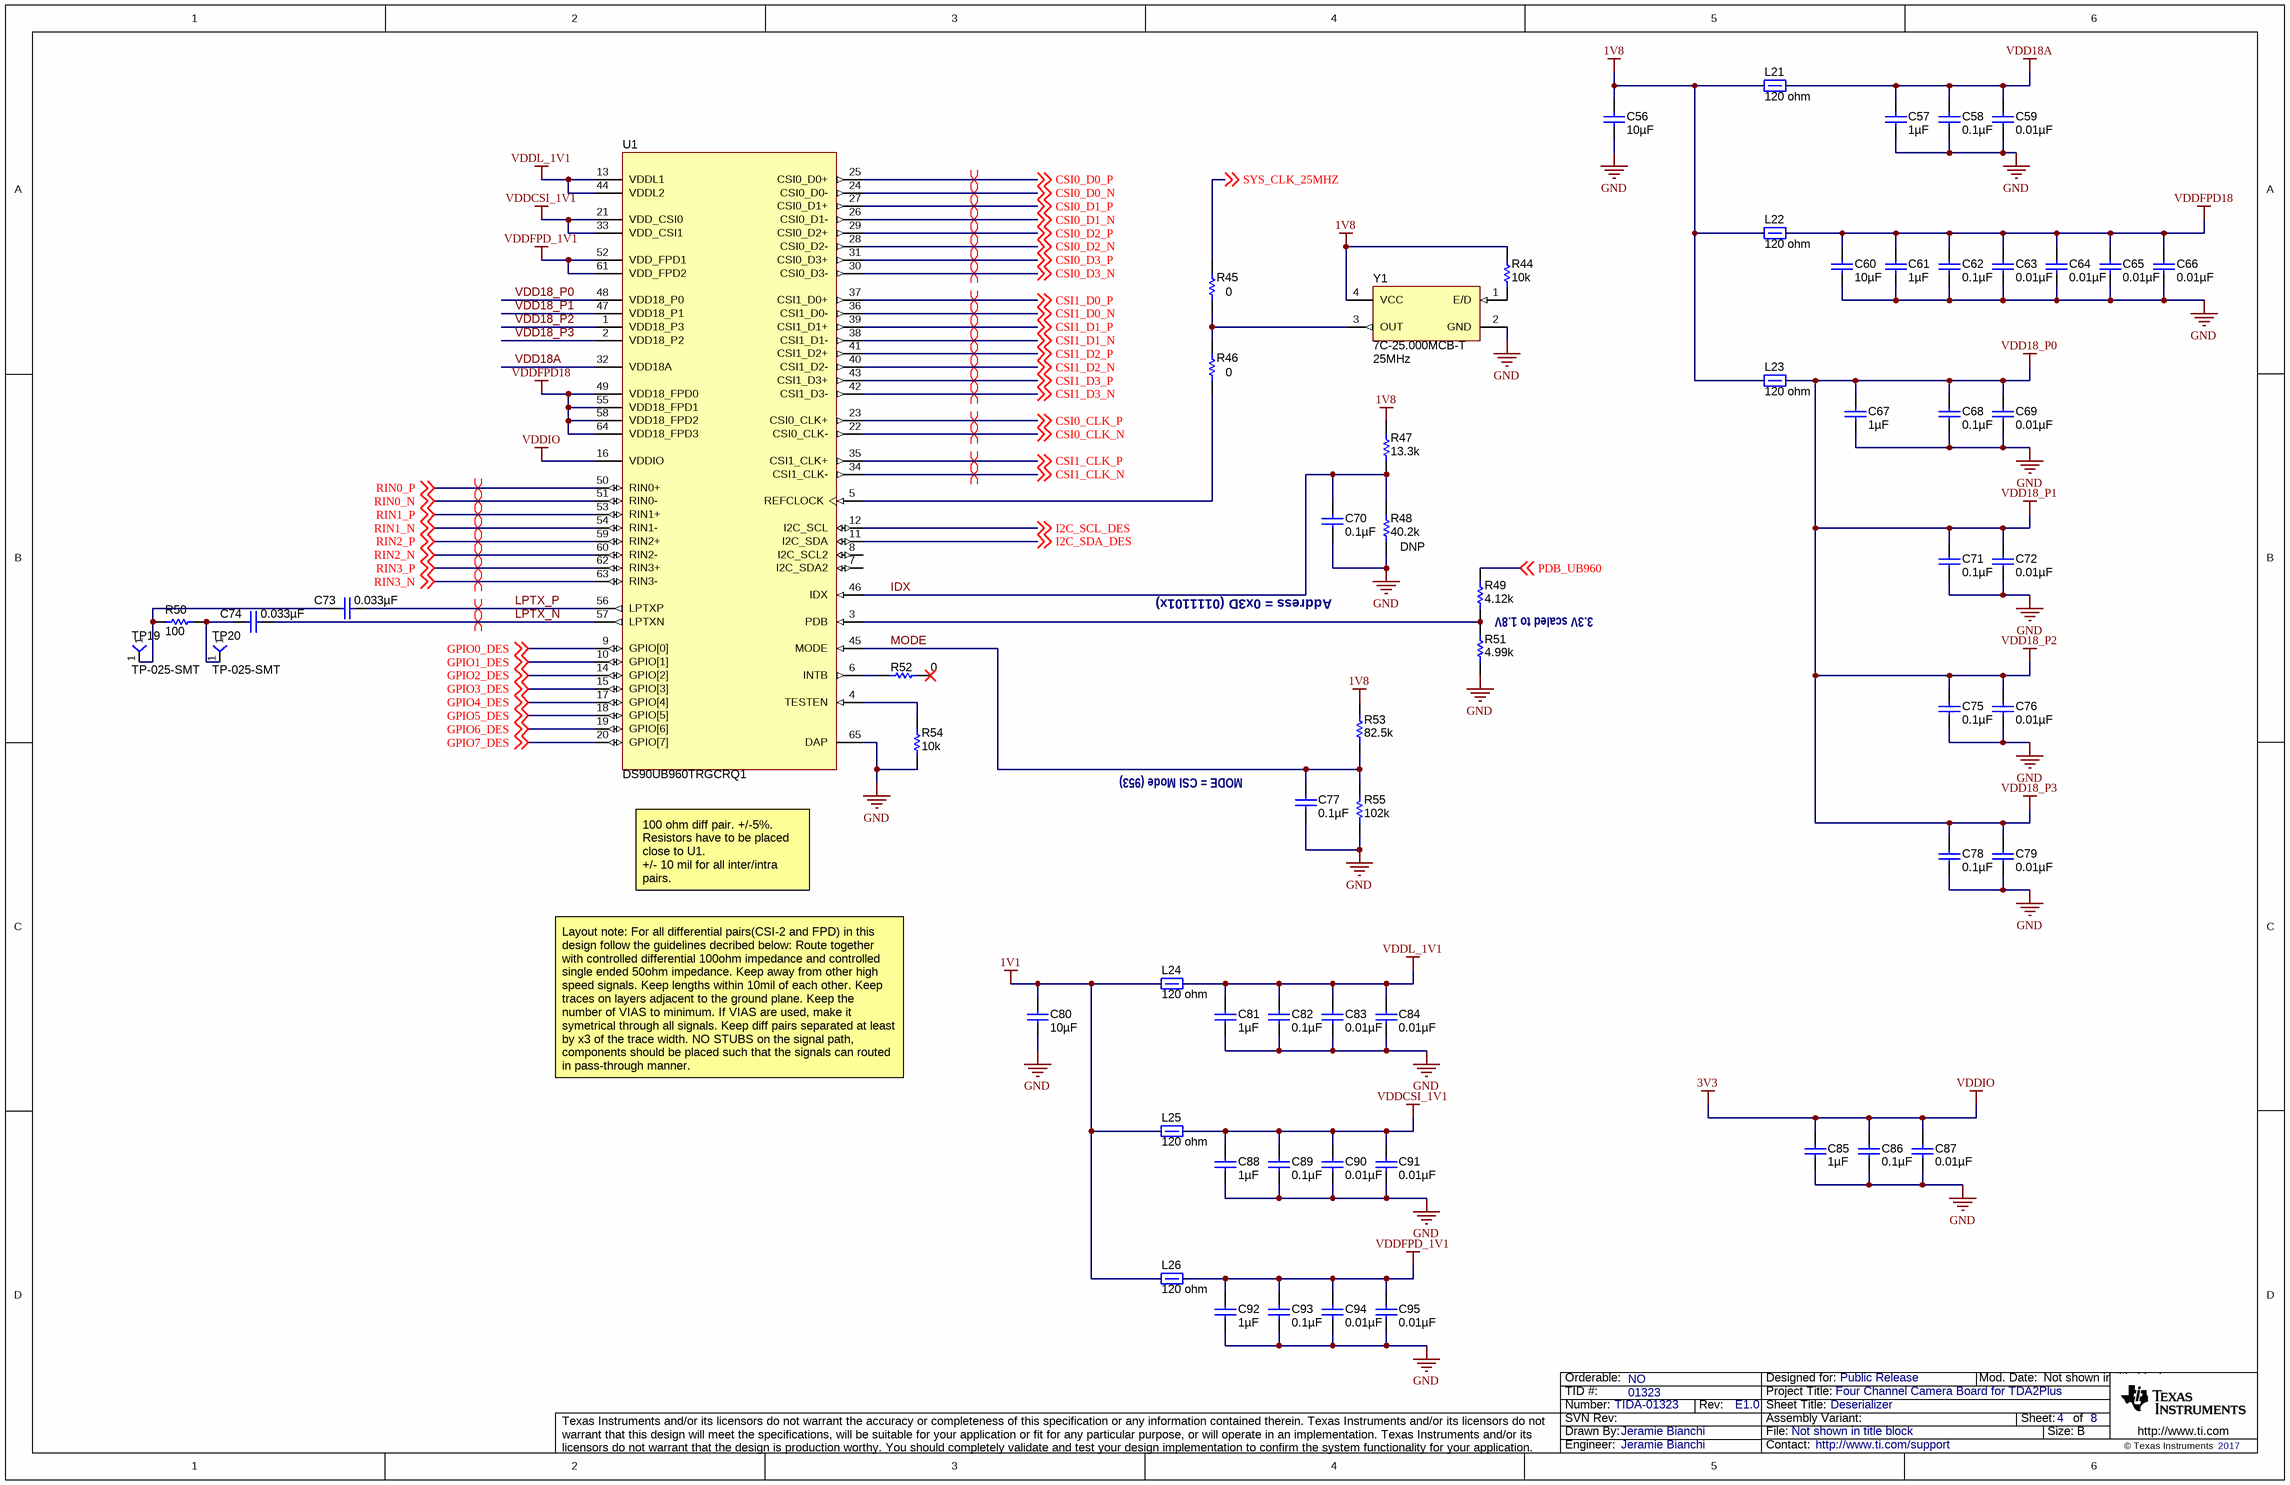
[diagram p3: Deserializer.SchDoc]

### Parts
C56  ValueDisplayed: 10µF  [0805_HV]  (hidden comment: CL21A106KAFN3NE)
C57  ValueDisplayed: 1µF  [0402]  (hidden comment: C1005JB1V105K050BC)
C58  ValueDisplayed: 0.1µF  [0603]  (hidden comment: CGA2B3X7R1H104K050BB)
C59  ValueDisplayed: 0.01µF  [0402]  (hidden comment: GCM155R71H103KA55D)
C60  ValueDisplayed: 10µF  [0805_HV]  (hidden comment: CL21A106KAFN3NE)
C61  ValueDisplayed: 1µF  [0402]  (hidden comment: C1005JB1V105K050BC)
C62  ValueDisplayed: 0.1µF  [0603]  (hidden comment: CGA2B3X7R1H104K050BB)
C63  ValueDisplayed: 0.01µF  [0402]  (hidden comment: GCM155R71H103KA55D)
C64  ValueDisplayed: 0.01µF  [0402]  (hidden comment: GCM155R71H103KA55D)
C65  ValueDisplayed: 0.01µF  [0402]  (hidden comment: GCM155R71H103KA55D)
C66  ValueDisplayed: 0.01µF  [0402]  (hidden comment: GCM155R71H103KA55D)
C67  ValueDisplayed: 1µF  [0402]  (hidden comment: C1005JB1V105K050BC)
C68  ValueDisplayed: 0.1µF  [0603]  (hidden comment: CGA2B3X7R1H104K050BB)
C69  ValueDisplayed: 0.01µF  [0402]  (hidden comment: GCM155R71H103KA55D)
C70  ValueDisplayed: 0.1µF  [0402]  (hidden comment: C1005X7R1H104K050BB)
C71  ValueDisplayed: 0.1µF  [0603]  (hidden comment: CGA2B3X7R1H104K050BB)
C72  ValueDisplayed: 0.01µF  [0402]  (hidden comment: GCM155R71H103KA55D)
C73  ValueDisplayed: 0.033µF  [0402]  (hidden comment: CGA2B3X7R1H333K050BB)
C74  ValueDisplayed: 0.033µF  [0402]  (hidden comment: CGA2B3X7R1H333K050BB)
C75  ValueDisplayed: 0.1µF  [0603]  (hidden comment: CGA2B3X7R1H104K050BB)
C76  ValueDisplayed: 0.01µF  [0402]  (hidden comment: GCM155R71H103KA55D)
C77  ValueDisplayed: 0.1µF  [0402]  (hidden comment: C1005X7R1H104K050BB)
C78  ValueDisplayed: 0.1µF  [0603]  (hidden comment: CGA2B3X7R1H104K050BB)
C79  ValueDisplayed: 0.01µF  [0402]  (hidden comment: GCM155R71H103KA55D)
C80  ValueDisplayed: 10µF  [0805_HV]  (hidden comment: CL21A106KAFN3NE)
C81  ValueDisplayed: 1µF  [0402]  (hidden comment: C1005JB1V105K050BC)
C82  ValueDisplayed: 0.1µF  [0603]  (hidden comment: CGA2B3X7R1H104K050BB)
C83  ValueDisplayed: 0.01µF  [0402]  (hidden comment: GCM155R71H103KA55D)
C84  ValueDisplayed: 0.01µF  [0402]  (hidden comment: GCM155R71H103KA55D)
C85  ValueDisplayed: 1µF  [0402]  (hidden comment: C1005JB1V105K050BC)
C86  ValueDisplayed: 0.1µF  [0603]  (hidden comment: CGA2B3X7R1H104K050BB)
C87  ValueDisplayed: 0.01µF  [0402]  (hidden comment: GCM155R71H103KA55D)
C88  ValueDisplayed: 1µF  [0402]  (hidden comment: C1005JB1V105K050BC)
C89  ValueDisplayed: 0.1µF  [0603]  (hidden comment: CGA2B3X7R1H104K050BB)
C90  ValueDisplayed: 0.01µF  [0402]  (hidden comment: GCM155R71H103KA55D)
C91  ValueDisplayed: 0.01µF  [0402]  (hidden comment: GCM155R71H103KA55D)
C92  ValueDisplayed: 1µF  [0402]  (hidden comment: C1005JB1V105K050BC)
C93  ValueDisplayed: 0.1µF  [0603]  (hidden comment: CGA2B3X7R1H104K050BB)
C94  ValueDisplayed: 0.01µF  [0402]  (hidden comment: GCM155R71H103KA55D)
C95  ValueDisplayed: 0.01µF  [0402]  (hidden comment: GCM155R71H103KA55D)
L21  value 120 ohm  [0603]  (hidden comment: BLM18SG121TN1D)
L22  value 120 ohm  [0603]  (hidden comment: BLM18SG121TN1D)
L23  value 120 ohm  [0603]  (hidden comment: BLM18SG121TN1D)
L24  value 120 ohm  [0603]  (hidden comment: BLM18SG121TN1D)
L25  value 120 ohm  [0603]  (hidden comment: BLM18SG121TN1D)
L26  value 120 ohm  [0603]  (hidden comment: BLM18SG121TN1D)
R44  value 10k  [0402]  (hidden comment: CRCW040210K0JNED)
R45  ValueDisplayed: 0  [0402]  (hidden comment: ERJ-2GE0R00X)
R46  ValueDisplayed: 0  [0402]  (hidden comment: ERJ-2GE0R00X)
R47  ValueDisplayed: 13.3k  [0402]  (hidden comment: CRCW040213K3FKED)
R48  ValueDisplayed: 40.2k  Text: DNP  [0402]  (hidden comment: CRCW040240K2FKED)  (no BOM)
R49  ValueDisplayed: 4.12k  [0402]  (hidden comment: CRCW04024K12FKED)
R50  value 100  [0402]  (hidden comment: CRCW0402100RFKED)
R51  ValueDisplayed: 4.99k  [0402]  (hidden comment: CRCW04024K99FKED)
R52  value 0  [0402]  (hidden comment: ERJ-2GE0R00X)
R53  ValueDisplayed: 82.5k  [0402]  (hidden comment: CRCW040282K5FKED)
R54  value 10k  [0402]  (hidden comment: CRCW040210K0JNED)
R55  ValueDisplayed: 102k  [0402]  (hidden comment: CRCW0402102KFKED)
TP19  TP-025-SMT  [TP_25MIL-SMT]
TP20  TP-025-SMT  [TP_25MIL-SMT]
U1  DS90UB960TRGCRQ1  [RGC0064G]
Y1  7C-25.000MCB-T  Frequency: 25MHz  [TXC_7C]

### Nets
1V1: C80.1 L24.1 L25.1 L26.1
1V8: C56.1 L21.1 L22.1 L23.1 R44.1 R47.2 R53.2 Y1.4(VCC)
3V3: C85.1 C86.1 C87.1 U1.16(VDDIO)  [also labelled VDDIO]
GND: C56.2 C57.2 C58.2 C59.2 C60.2 C61.2 C62.2 C63.2 C64.2 C65.2 C66.2 C67.2 C68.2 C69.2 C70.2 C71.2 C72.2 C75.2 C76.2 C77.2 C78.2 C79.2 C80.2 C81.2 C82.2 C83.2 C84.2 C85.2 C86.2 C87.2 C88.2 C89.2 C90.2 C91.2 C92.2 C93.2 C94.2 C95.2 R48.1 R51.1 R54.1 R55.1 U1.65(DAP) Y1.2(GND)
VDD18_P0: C67.1 C68.1 C69.1 C71.1 C72.1 C75.1 C76.1 C78.1 C79.1 L23.2 U1.1(VDD18_P3) U1.2(VDD18_P2) U1.47(VDD18_P1) U1.48(VDD18_P0)  [also labelled VDD18_P1, VDD18_P2, VDD18_P3]
VDD18A: C57.1 C58.1 C59.1 L21.2 U1.32(VDD18A)
VDDCSI_1V1: C88.1 C89.1 C90.1 C91.1 L25.2 U1.21(VDD_CSI0) U1.33(VDD_CSI1)
VDDFPD18: C60.1 C61.1 C62.1 C63.1 C64.1 C65.1 C66.1 L22.2 U1.49(VDD18_FPD0) U1.55(VDD18_FPD1) U1.58(VDD18_FPD2) U1.64(VDD18_FPD3)
VDDFPD_1V1: C92.1 C93.1 C94.1 C95.1 L26.2 U1.52(VDD_FPD1) U1.61(VDD_FPD2)
VDDL_1V1: C81.1 C82.1 C83.1 C84.1 L24.2 U1.13(VDDL1) U1.44(VDDL2)
CSI0_CLK_N: U1.22(CSI0_CLK-) ; off-sheet CSI0_CLK_N
CSI0_CLK_P: U1.23(CSI0_CLK+) ; off-sheet CSI0_CLK_P
CSI0_D0_N: U1.24(CSI0_D0-) ; off-sheet CSI0_D0_N
CSI0_D0_P: U1.25(CSI0_D0+) ; off-sheet CSI0_D0_P
CSI0_D1_N: U1.26(CSI0_D1-) ; off-sheet CSI0_D1_N
CSI0_D1_P: U1.27(CSI0_D1+) ; off-sheet CSI0_D1_P
CSI0_D2_N: U1.28(CSI0_D2-) ; off-sheet CSI0_D2_N
CSI0_D2_P: U1.29(CSI0_D2+) ; off-sheet CSI0_D2_P
CSI0_D3_N: U1.30(CSI0_D3-) ; off-sheet CSI0_D3_N
CSI0_D3_P: U1.31(CSI0_D3+) ; off-sheet CSI0_D3_P
CSI1_CLK_N: U1.34(CSI1_CLK-) ; off-sheet CSI1_CLK_N
CSI1_CLK_P: U1.35(CSI1_CLK+) ; off-sheet CSI1_CLK_P
CSI1_D0_N: U1.36(CSI1_D0-) ; off-sheet CSI1_D0_N
CSI1_D0_P: U1.37(CSI1_D0+) ; off-sheet CSI1_D0_P
CSI1_D1_N: U1.38(CSI1_D1-) ; off-sheet CSI1_D1_N
CSI1_D1_P: U1.39(CSI1_D1+) ; off-sheet CSI1_D1_P
CSI1_D2_N: U1.40(CSI1_D2-) ; off-sheet CSI1_D2_N
CSI1_D2_P: U1.41(CSI1_D2+) ; off-sheet CSI1_D2_P
CSI1_D3_N: U1.42(CSI1_D3-) ; off-sheet CSI1_D3_N
CSI1_D3_P: U1.43(CSI1_D3+) ; off-sheet CSI1_D3_P
GPIO0_DES: U1.9(GPIO[0]) ; off-sheet GPIO0_DES
GPIO1_DES: U1.10(GPIO[1]) ; off-sheet GPIO1_DES
GPIO2_DES: U1.14(GPIO[2]) ; off-sheet GPIO2_DES
GPIO3_DES: U1.15(GPIO[3]) ; off-sheet GPIO3_DES
GPIO4_DES: U1.17(GPIO[4]) ; off-sheet GPIO4_DES
GPIO5_DES: U1.18(GPIO[5]) ; off-sheet GPIO5_DES
GPIO6_DES: U1.19(GPIO[6]) ; off-sheet GPIO6_DES
GPIO7_DES: U1.20(GPIO[7]) ; off-sheet GPIO7_DES
I2C_SCL_DES: U1.12(I2C_SCL) ; off-sheet I2C_SCL_DES
I2C_SDA_DES: U1.11(I2C_SDA) ; off-sheet I2C_SDA_DES
IDX: C70.1 R47.1 R48.2 U1.46(IDX)
LPTX_N: C74.1 U1.57(LPTXN)
LPTX_P: C73.1 U1.56(LPTXP)
MODE: C77.1 R53.1 R55.2 U1.45(MODE)
PDB_UB960: R49.2 ; off-sheet PDB_UB960
RIN0_N: U1.51(RIN0-) ; off-sheet RIN0_N
RIN0_P: U1.50(RIN0+) ; off-sheet RIN0_P
RIN1_N: U1.54(RIN1-) ; off-sheet RIN1_N
RIN1_P: U1.53(RIN1+) ; off-sheet RIN1_P
RIN2_N: U1.60(RIN2-) ; off-sheet RIN2_N
RIN2_P: U1.59(RIN2+) ; off-sheet RIN2_P
RIN3_N: U1.63(RIN3-) ; off-sheet RIN3_N
RIN3_P: U1.62(RIN3+) ; off-sheet RIN3_P
SYS_CLK_25MHZ: R45.2 ; off-sheet SYS_CLK_25MHZ
NetC73_2: C73.2 R50.2 TP19.1
NetC74_2: C74.2 R50.1 TP20.1
NetR44_2: R44.2 Y1.1(E/D)
NetR45_1: R45.1 R46.2 Y1.3(OUT)
NetR46_1: R46.1 U1.5(REFCLOCK)
NetR49_1: R49.1 R51.2 U1.3(PDB)
NetR52_1: R52.1 U1.6(INTB)
NetR54_2: R54.2 U1.4(TESTEN)

Not connected (* = marked no-connect by the designer): R52 2*; U1 7(I2C_SDA2) 8(I2C_SCL2)

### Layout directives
differential pair: CSI0_CLK_N, CSI0_CLK_P, CSI0_D0_N, CSI0_D0_P, CSI0_D1_N, CSI0_D1_P, CSI0_D2_N, CSI0_D2_P, CSI0_D3_N, CSI0_D3_P, CSI1_CLK_N, CSI1_CLK_P, CSI1_D0_N, CSI1_D0_P, CSI1_D1_N, CSI1_D1_P, CSI1_D2_N, CSI1_D2_P, CSI1_D3_N, CSI1_D3_P, LPTX_N, LPTX_P, RIN0_N, RIN0_P, RIN1_N, RIN1_P, RIN2_N, RIN2_P, RIN3_N, RIN3_P

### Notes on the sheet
- Address = 0x3D (0111101x)
- 3.3V scaled to 1.8V
- (near C77) MODE = CSI Mode (953)
- 100 ohm diff pair. +/-5%.
  Resistors have to be placed close to U1.
  +/- 10 mil for all inter/intra pairs.
- Layout note: For all differential pairs(CSI-2 and FPD) in this design follow the guidelines decribed below: Route together with controlled differential 100ohm impedance and controlled single ended 50ohm impedance. Keep away from other high speed signals. Keep lengths within 10mil of each other. Keep traces on layers adjacent to the ground plane. Keep the number of VIAS to minimum. If VIAS are used, make it symetrical through all signals. Keep diff pairs separated at least by x3 of the trace width. NO STUBS on the signal path, components should be placed such that the signals can routed in pass-through manner.

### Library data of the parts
C56 C60 C80 = CL21A106KAFN3NE: CAP, CERM, 10 µF, 25 V, +/- 10%, X5R, 0805; Manufacturer: Samsung; Polarized: N; CompType: Capacitor; Value: 10uF; U/M: EA; Cap_F: 0.00001; Tolerance_%: 10; Value1: Unknown; VDC_V: 25; Value2: 25V; TaMin_C: -55; TaMax_C: 85; Cap_Case: 0805
C57 C61 C67 C81 C85 C88 C92 = C1005JB1V105K050BC: as C47 on sheet Bucks
C58 C62 C68 C71 C75 C78 C82 C86 C89 C93 = GRM188R71C474KA88D: CAP, CERM, 0.1uF, 50V, +/-10%, X7R, 0402; Manufacturer: TDK; Polarized: N; CompType: Capacitor; U/M: EA; Cap_F: 0.00000001; Tolerance_%: 10; Value1: Unknown; TaMin_C: -55; TaMax_C: 125; Cap_Case: 0402
C59 C63-C66 C69 C72 C76 C79 C83 C84 C87 C90 C91 C94 C95 = GCM155R71H103KA55D: CAP, CERM, 0.01uF, 50V, +/-10%, C0G/NP0, 0402; Manufacturer: MuRata; Polarized: N; CompType: Capacitor; U/M: EA; Cap_F: 0.00000001; Tolerance_%: 10; Value1: Unknown; VDC_V: 50; TaMin_C: -55; TaMax_C: 125
C70 C77 = C1005X7R1H104K050BB: CAP, CERM, 0.1 µF, 50 V, +/- 10%, X7R, 0402; Manufacturer: TDK; Polarized: N; CompType: Capacitor; Value: 0.1uF; U/M: EA; Cap_F: 0.0000001; Tolerance_%: 10; ESR_ohm: 0.039064; Value1: 0.039064 ohm; VDC_V: 50; Value2: 50V; IRMS_A: 0.814669; TaMin_C: -55; TaMax_C: 125; SizeArea_mm2: 0.5; SizeAreaWB_mm2: 3; SizeX_mm: 1; SizeZ_mm: 0.6; AEC Category: Q200
C73 C74 = CGA2B3X7R1H333K050BB: CAP, CERM, 0.033 µF, 50 V, +/- 10%, X7R, 0402; Manufacturer: TDK; Polarized: N; CompType: Capacitor; Value: 0.033uF; U/M: EA; Cap_F: 0.000000033; Tolerance_%: 10; Value1: Unknown; VDC_V: 50; Value2: 50V; TaMin_C: -55; TaMax_C: 125
L21 = BLM18SG121TN1D: Ferrite Bead, 120 ohm @ 100 MHz, 3 A, 0603; Manufacturer: MuRata; Imax_A: 3; DCR_ohm: 0.025; Value1: 0.025 ohm; Value2: 3A; ZTyp@100MHz_Ohm: 120
L22-L26 = BLM18SG331TN1D: 1.5A Ferrite Bead, 330 ohm @ 100MHz, SMD; Manufacturer: MuRata; Imax_A: 3; DCR_ohm: 25milliiohm; Value1: 25 milliohm; Value2: 3A; ZTyp@100MHz_Ohm: 120; U/M: EA
R44 R54 = CRCW040210K0JNED: RES, 10k ohm, 5%, 0.063W, 0402; Manufacturer: Vishay-Dale; CompType: Resistor; Res_ohm: 10000; Value_Code: 10k0; Tolerance_%: 5; Power_W: 0.063; VDC_V: 50; TempCo: 200 ppm/C; EIA_Code: E24; U/M: EA
R45 R46 = ERJ-2GE0R00X: RES, 0, 5%, 0.063 W, 0402; Manufacturer: Panasonic; CompType: Resistor; Value: 0; Value_Code: 0000; Tolerance_%: 5; Power_W: 0.063; Value2: 0.063W; VDC_V: 50; TempCo: 600 ppm/C; EIA_Code: E24; U/M: EA
R47 = CRCW040213K3FKED: RES, 13.3 k, 1%, 0.063 W, 0402; Manufacturer: Vishay-Dale; CompType: Resistor; Value: 13.3k; Res_ohm: 13300; Value_Code: 13k3; Tolerance_%: 1; Power_W: 0.063; Value2: 0.063W; VDC_V: 50; TempCo: 100 ppm/C; EIA_Code: E96; U/M: EA
R48 = CRCW040240K2FKED: RES, 40.2 k, 1%, 0.063 W, 0402; Manufacturer: Vishay-Dale; CompType: Resistor; Value: 40.2k; Res_ohm: 40200; Value_Code: 40k2; Tolerance_%: 1; Power_W: 0.063; Value2: 0.063W; VDC_V: 50; TempCo: 100 ppm/C; EIA_Code: E96; U/M: EA
R49 = CRCW04024K12FKED: RES, 4.12 k, 1%, 0.063 W, 0402; Manufacturer: Vishay-Dale; CompType: Resistor; Value: 4.12k; Res_ohm: 4120; Value_Code: 4k12; Tolerance_%: 1; Power_W: 0.063; Value2: 0.063W; VDC_V: 50; TempCo: 100 ppm/C; EIA_Code: E96; U/M: EA
R50 = CRCW0402100RFKED: RES, 100 ohm, 1%, 0.063W, 0402; Manufacturer: Vishay-Dale; CompType: Resistor; Value_Code: 100R; Tolerance_%: 1; Power_W: 0.063; VDC_V: 50; TempCo: 100 ppm/C; EIA_Code: E96; U/M: EA
R51 = CRCW04024K99FKED: RES, 4.99 k, 1%, 0.063 W, 0402; Manufacturer: Vishay-Dale; CompType: Resistor; Value: 4.99k; Res_ohm: 4990; Value_Code: 4k99; Tolerance_%: 1; Power_W: 0.063; Value2: 0.063W; VDC_V: 50; TempCo: 100 ppm/C; EIA_Code: E96; U/M: EA
R52 = ERJ-2GE0R00X: RES, 0 ohm, 5%, 0.063W, 0402; Manufacturer: Panasonic; CompType: Resistor; Value_Code: 0000; Tolerance_%: 5; Power_W: 0.063; VDC_V: 50; TempCo: 600 ppm/C; EIA_Code: E24; U/M: EA
R53 = CRCW040282K5FKED: RES, 82.5 k, 1%, 0.063 W, AEC-Q200 Grade 0, 0402; Manufacturer: Vishay-Dale; CompType: Resistor; Value: 82.5k; Res_ohm: 82500; Value_Code: 82k5; Tolerance_%: 1; Power_W: 0.063; Value2: 0.063W; VDC_V: 50; TempCo: 100 ppm/C; EIA_Code: E96; U/M: EA; SizeArea_mm2: 0.5; SizeZ_mm: 0.6; AEC Category: Q200; AEC Qualified: Y; AEC Grade: 0; Green_Lifecycle: Active; Green_REACh: Passed
R55 = CRCW0402102KFKED: RES, 102 k, 1%, 0.063 W, 0402; Manufacturer: Vishay-Dale; CompType: Resistor; Value: 102k; Res_ohm: 102000; Tolerance_%: 1; Power_W: 0.063; Value2: 0.063W; VDC_V: 50; TempCo: 100 ppm/C; EIA_Code: E96; U/M: EA; SizeArea_mm2: 0.5; SizeZ_mm: 0.6; AEC Category: Q200; Green_Lifecycle: Active; Green_REACh: Passed
TP19 TP20 = TP-025-SMT: Test Point, O.025"; Manufacturer: STD; Value: STD
U1 = DS90UB960TRGCRQ1: FPD-Link III Camera Hub Deserializer, RGC0064G; Alternate PartNumber: DS90UB960TRGCTQ1; Manufacturer: Texas Instruments; SymbolCreator: Altium; SizeArea_mm2: 81; SizeAreaWB_mm2: 121; SizeX_mm: 9; SizeZ_mm: 1; CompType: IC; U/M: EA
Y1 = 7C-25.000MCB-T: XO, 25.000MHz, 2.5V, SMD; Manufacturer: TXC Corporation; SymbolCreator: a0411947; CompType: Oscillator; U/M: EA; TaMin_C: -40; TaMax_C: 85; Frequency Stability: ±50ppm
